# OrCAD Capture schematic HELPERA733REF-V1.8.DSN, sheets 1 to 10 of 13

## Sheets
1 00 Change log: title: HELPERA733_REF; rev: V1.8; company: szBaijie; note: Revision History
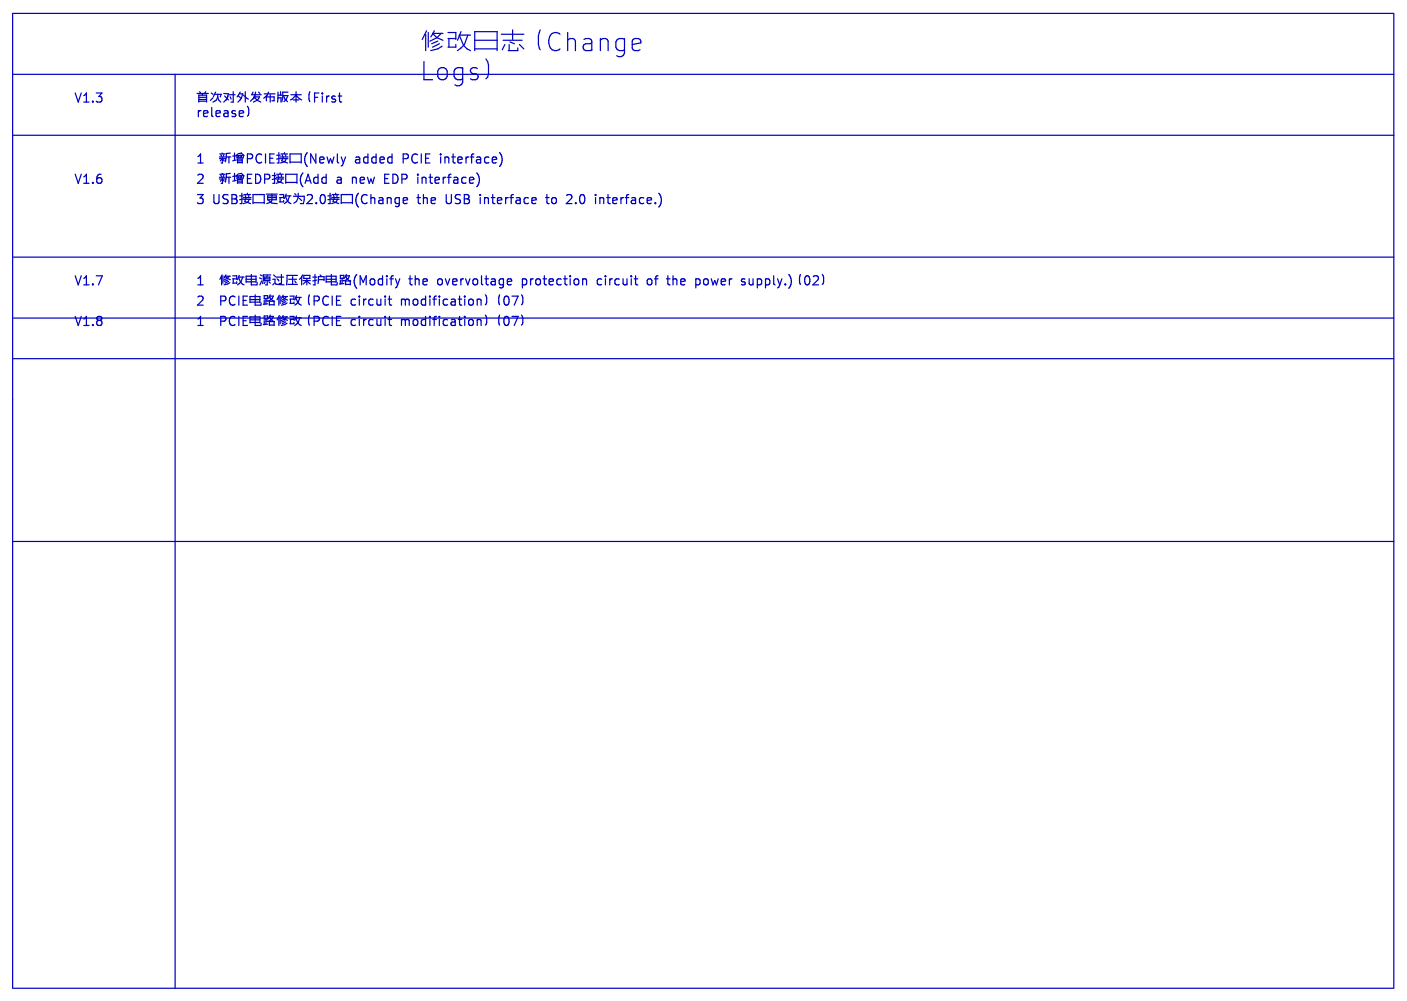
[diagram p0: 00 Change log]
2 01 CORE: size C; note: Core
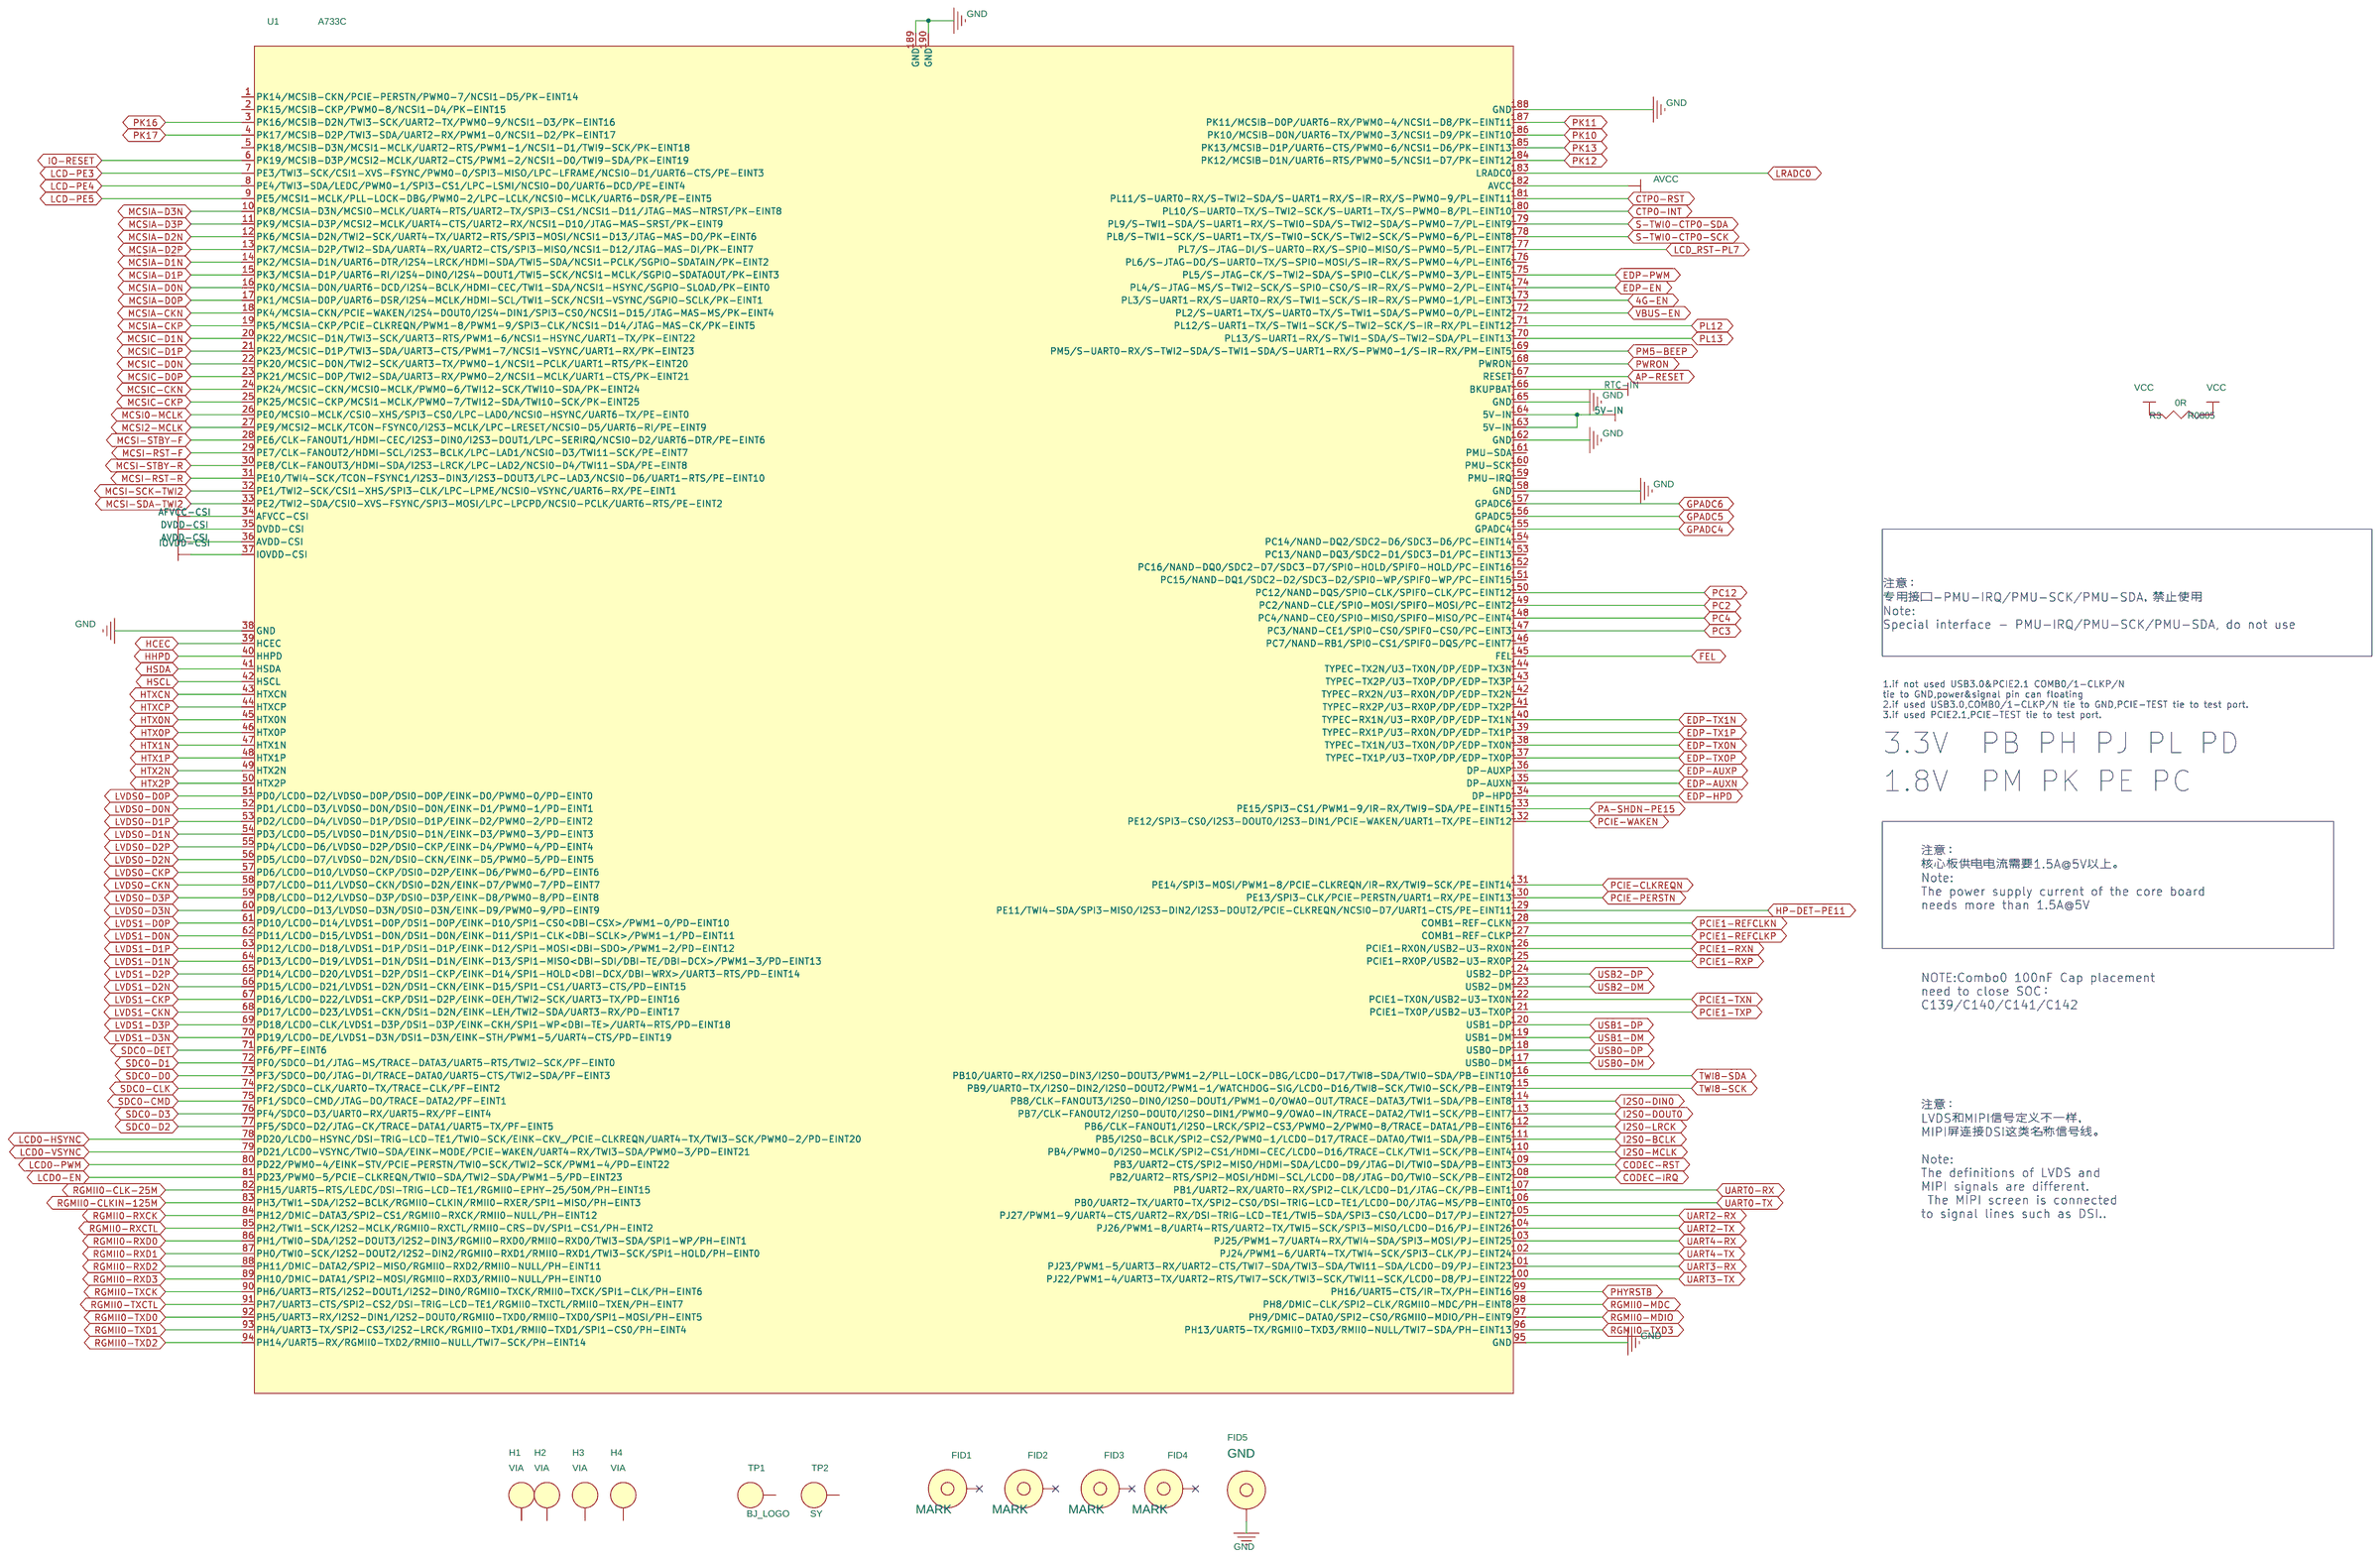
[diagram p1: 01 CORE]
3 02 Power: size B; note: Power
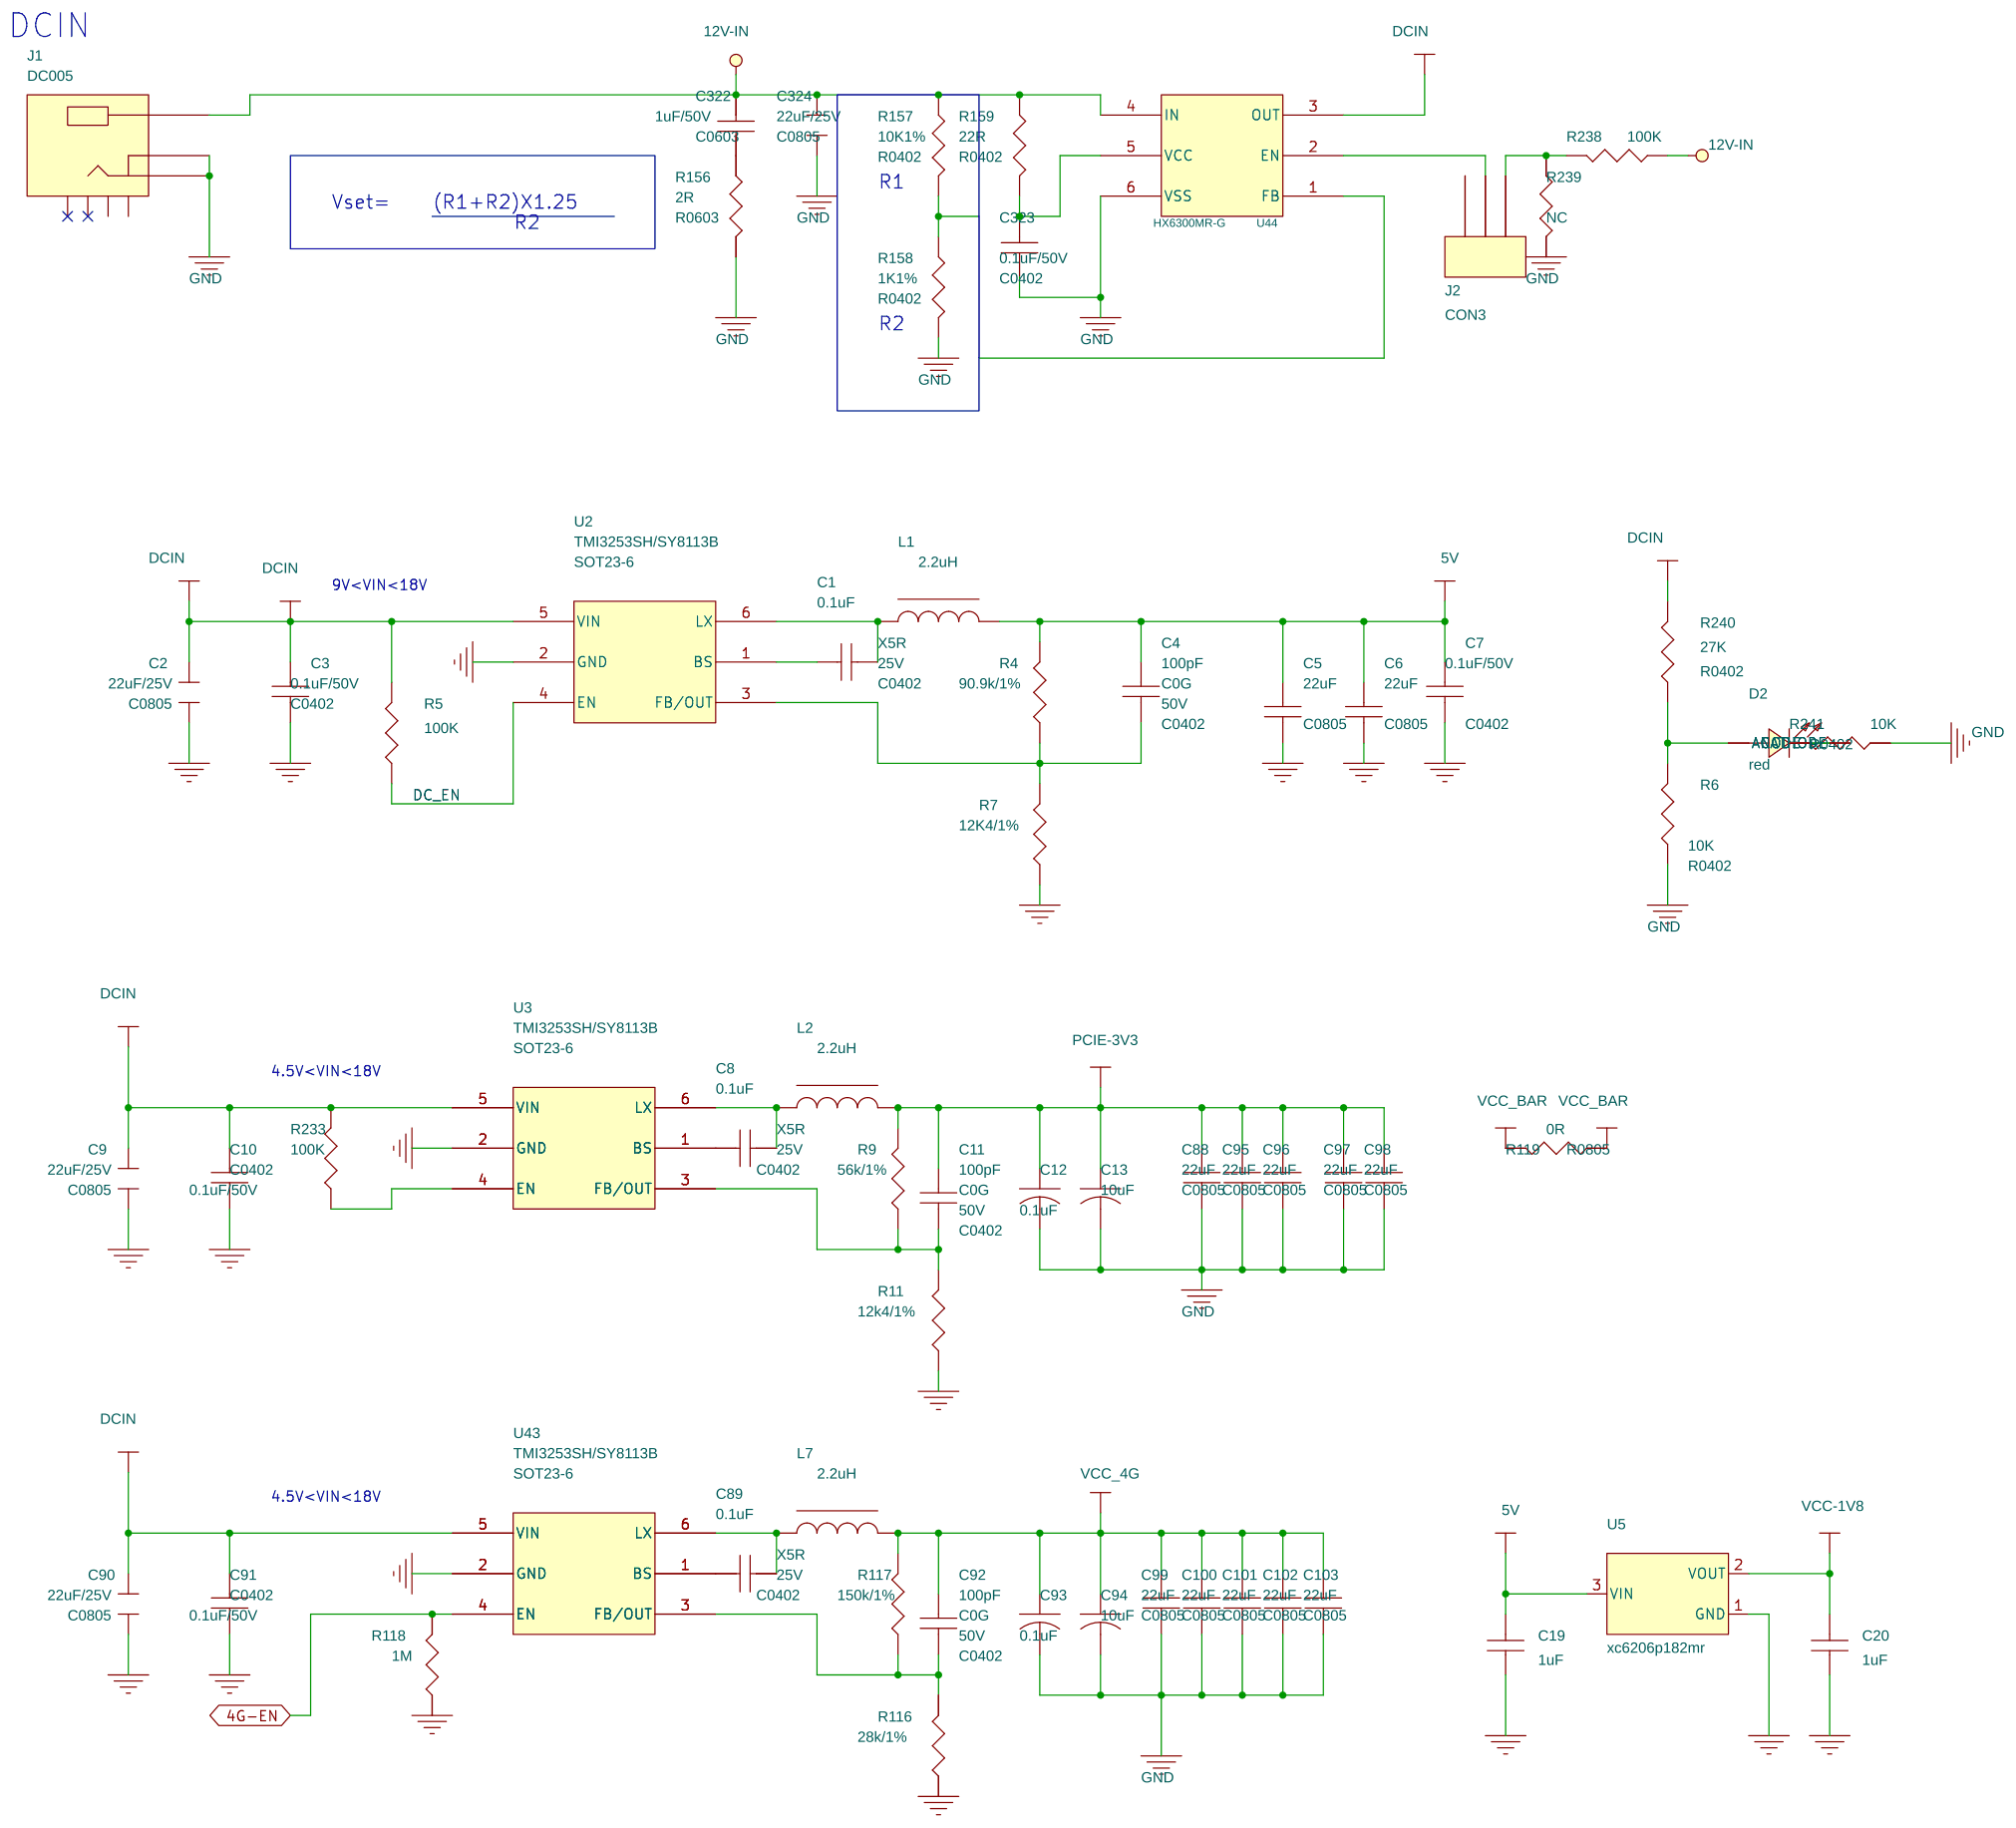
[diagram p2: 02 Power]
4 03 CAMERA: size Custom; note: Camera
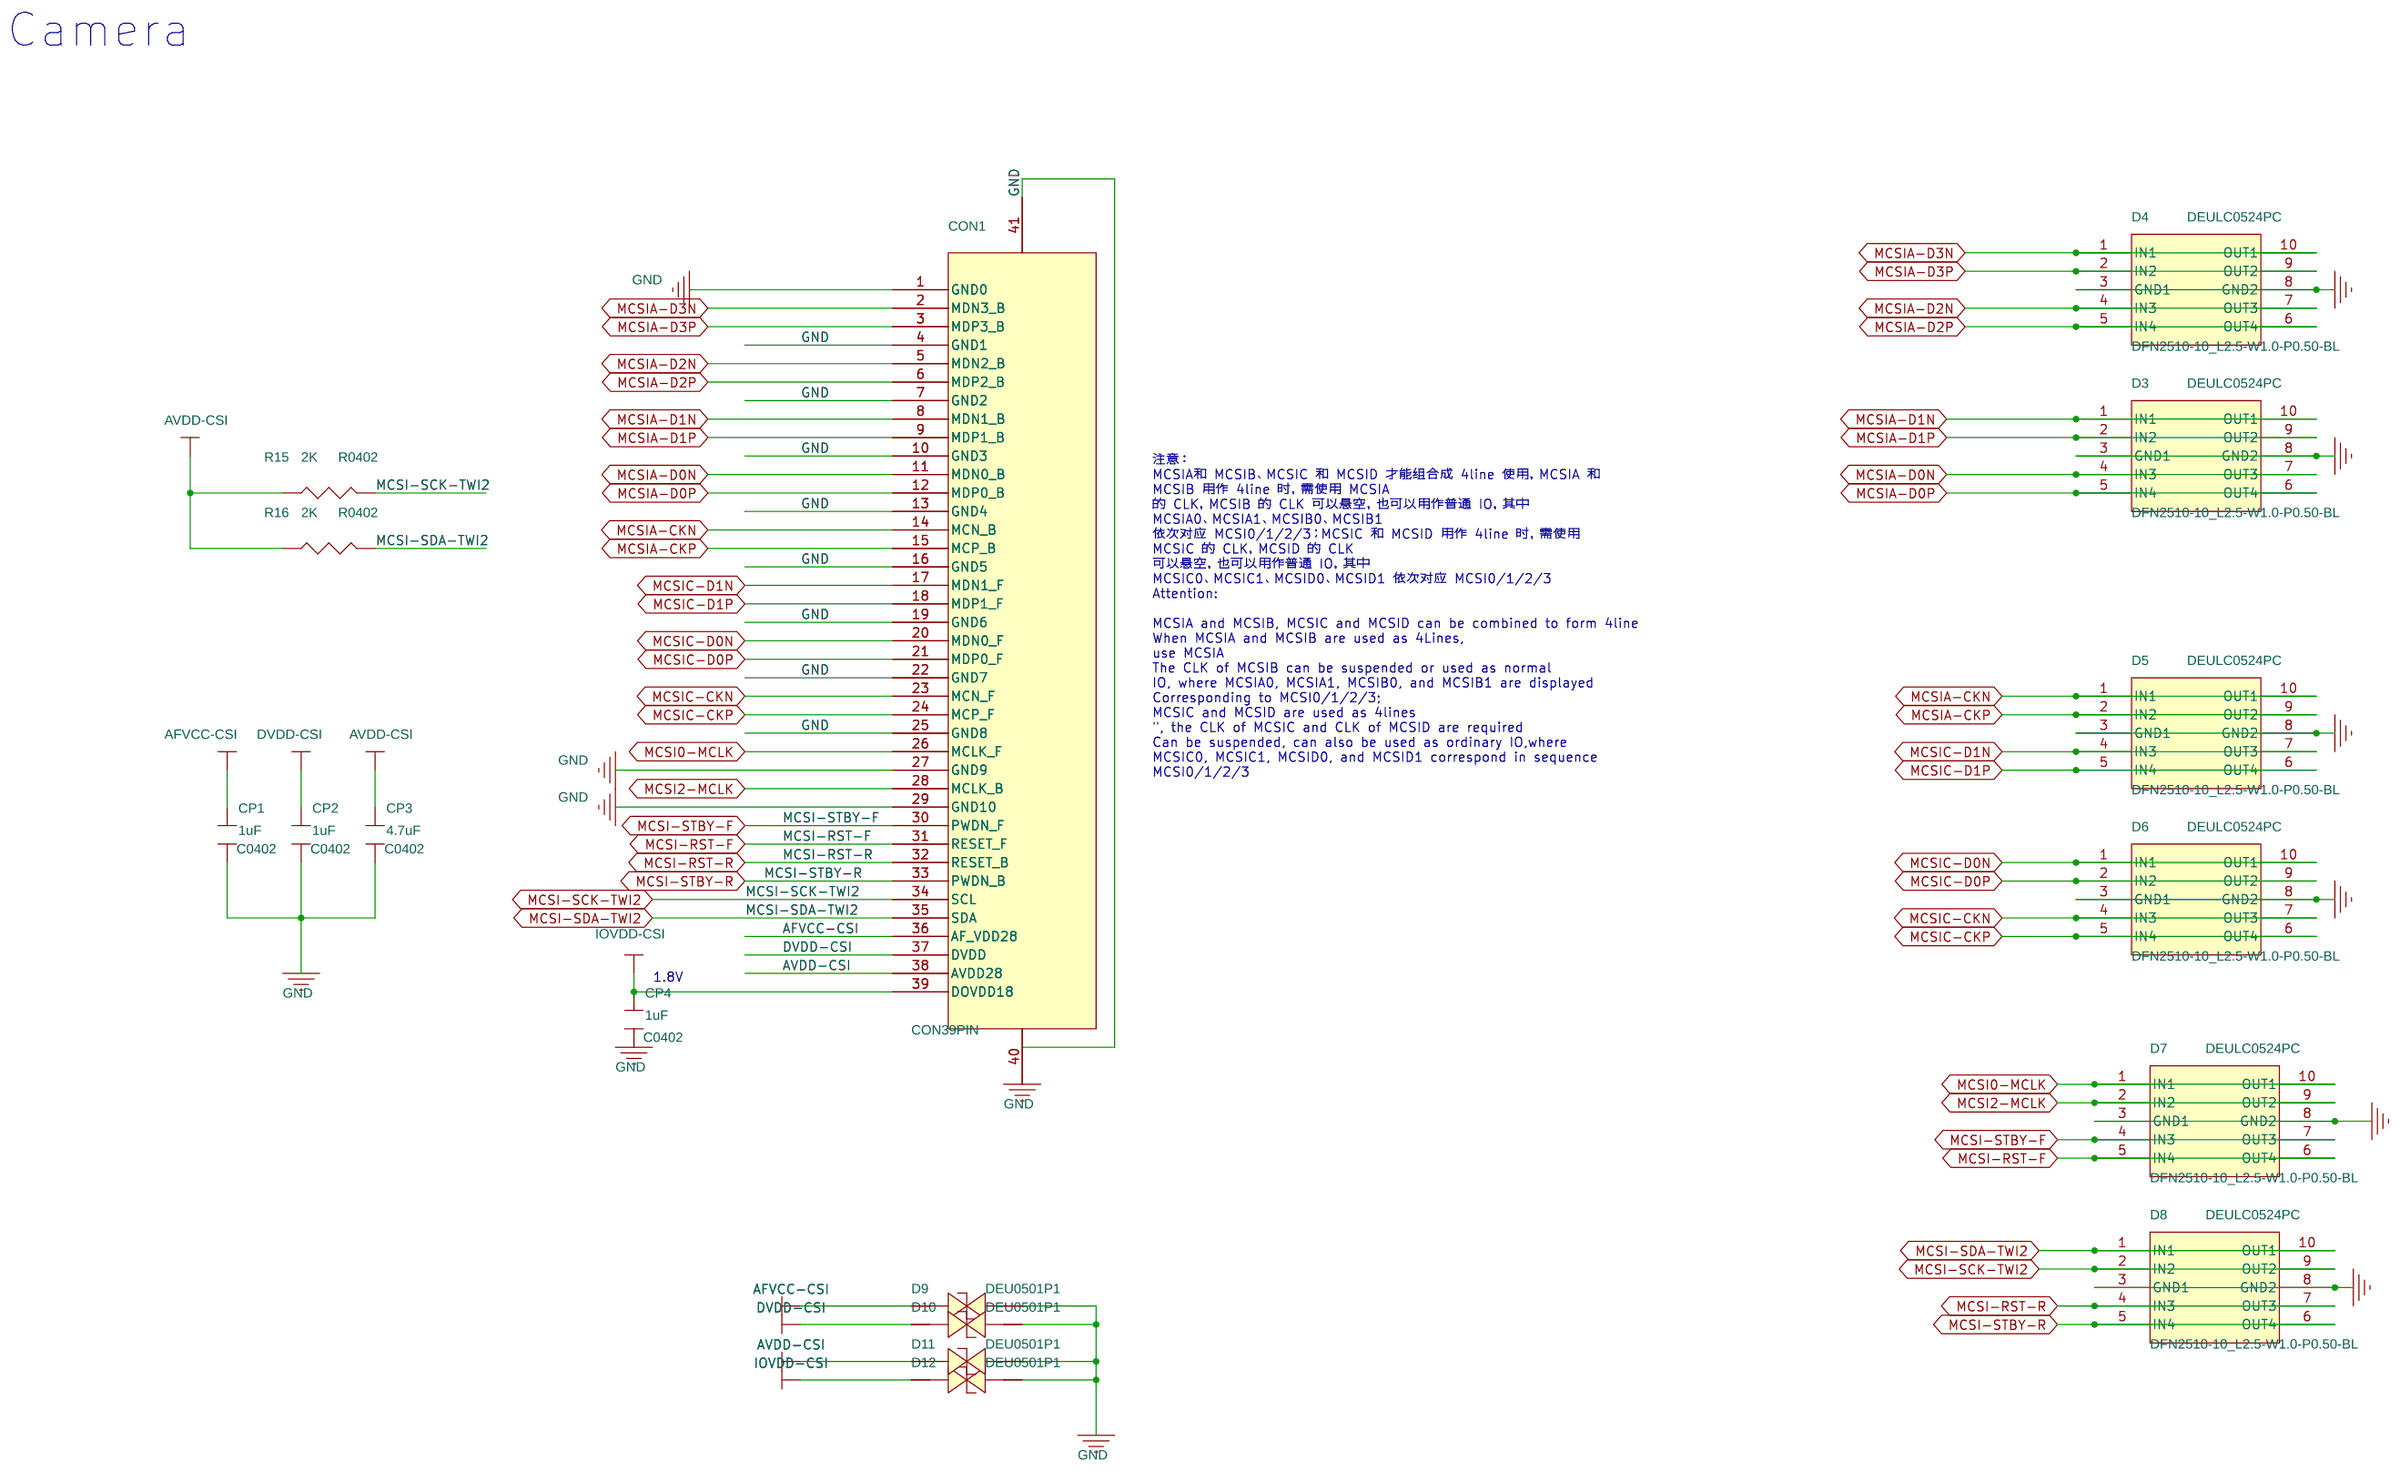
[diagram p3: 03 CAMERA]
5 04 LCD: size C; note: LCD
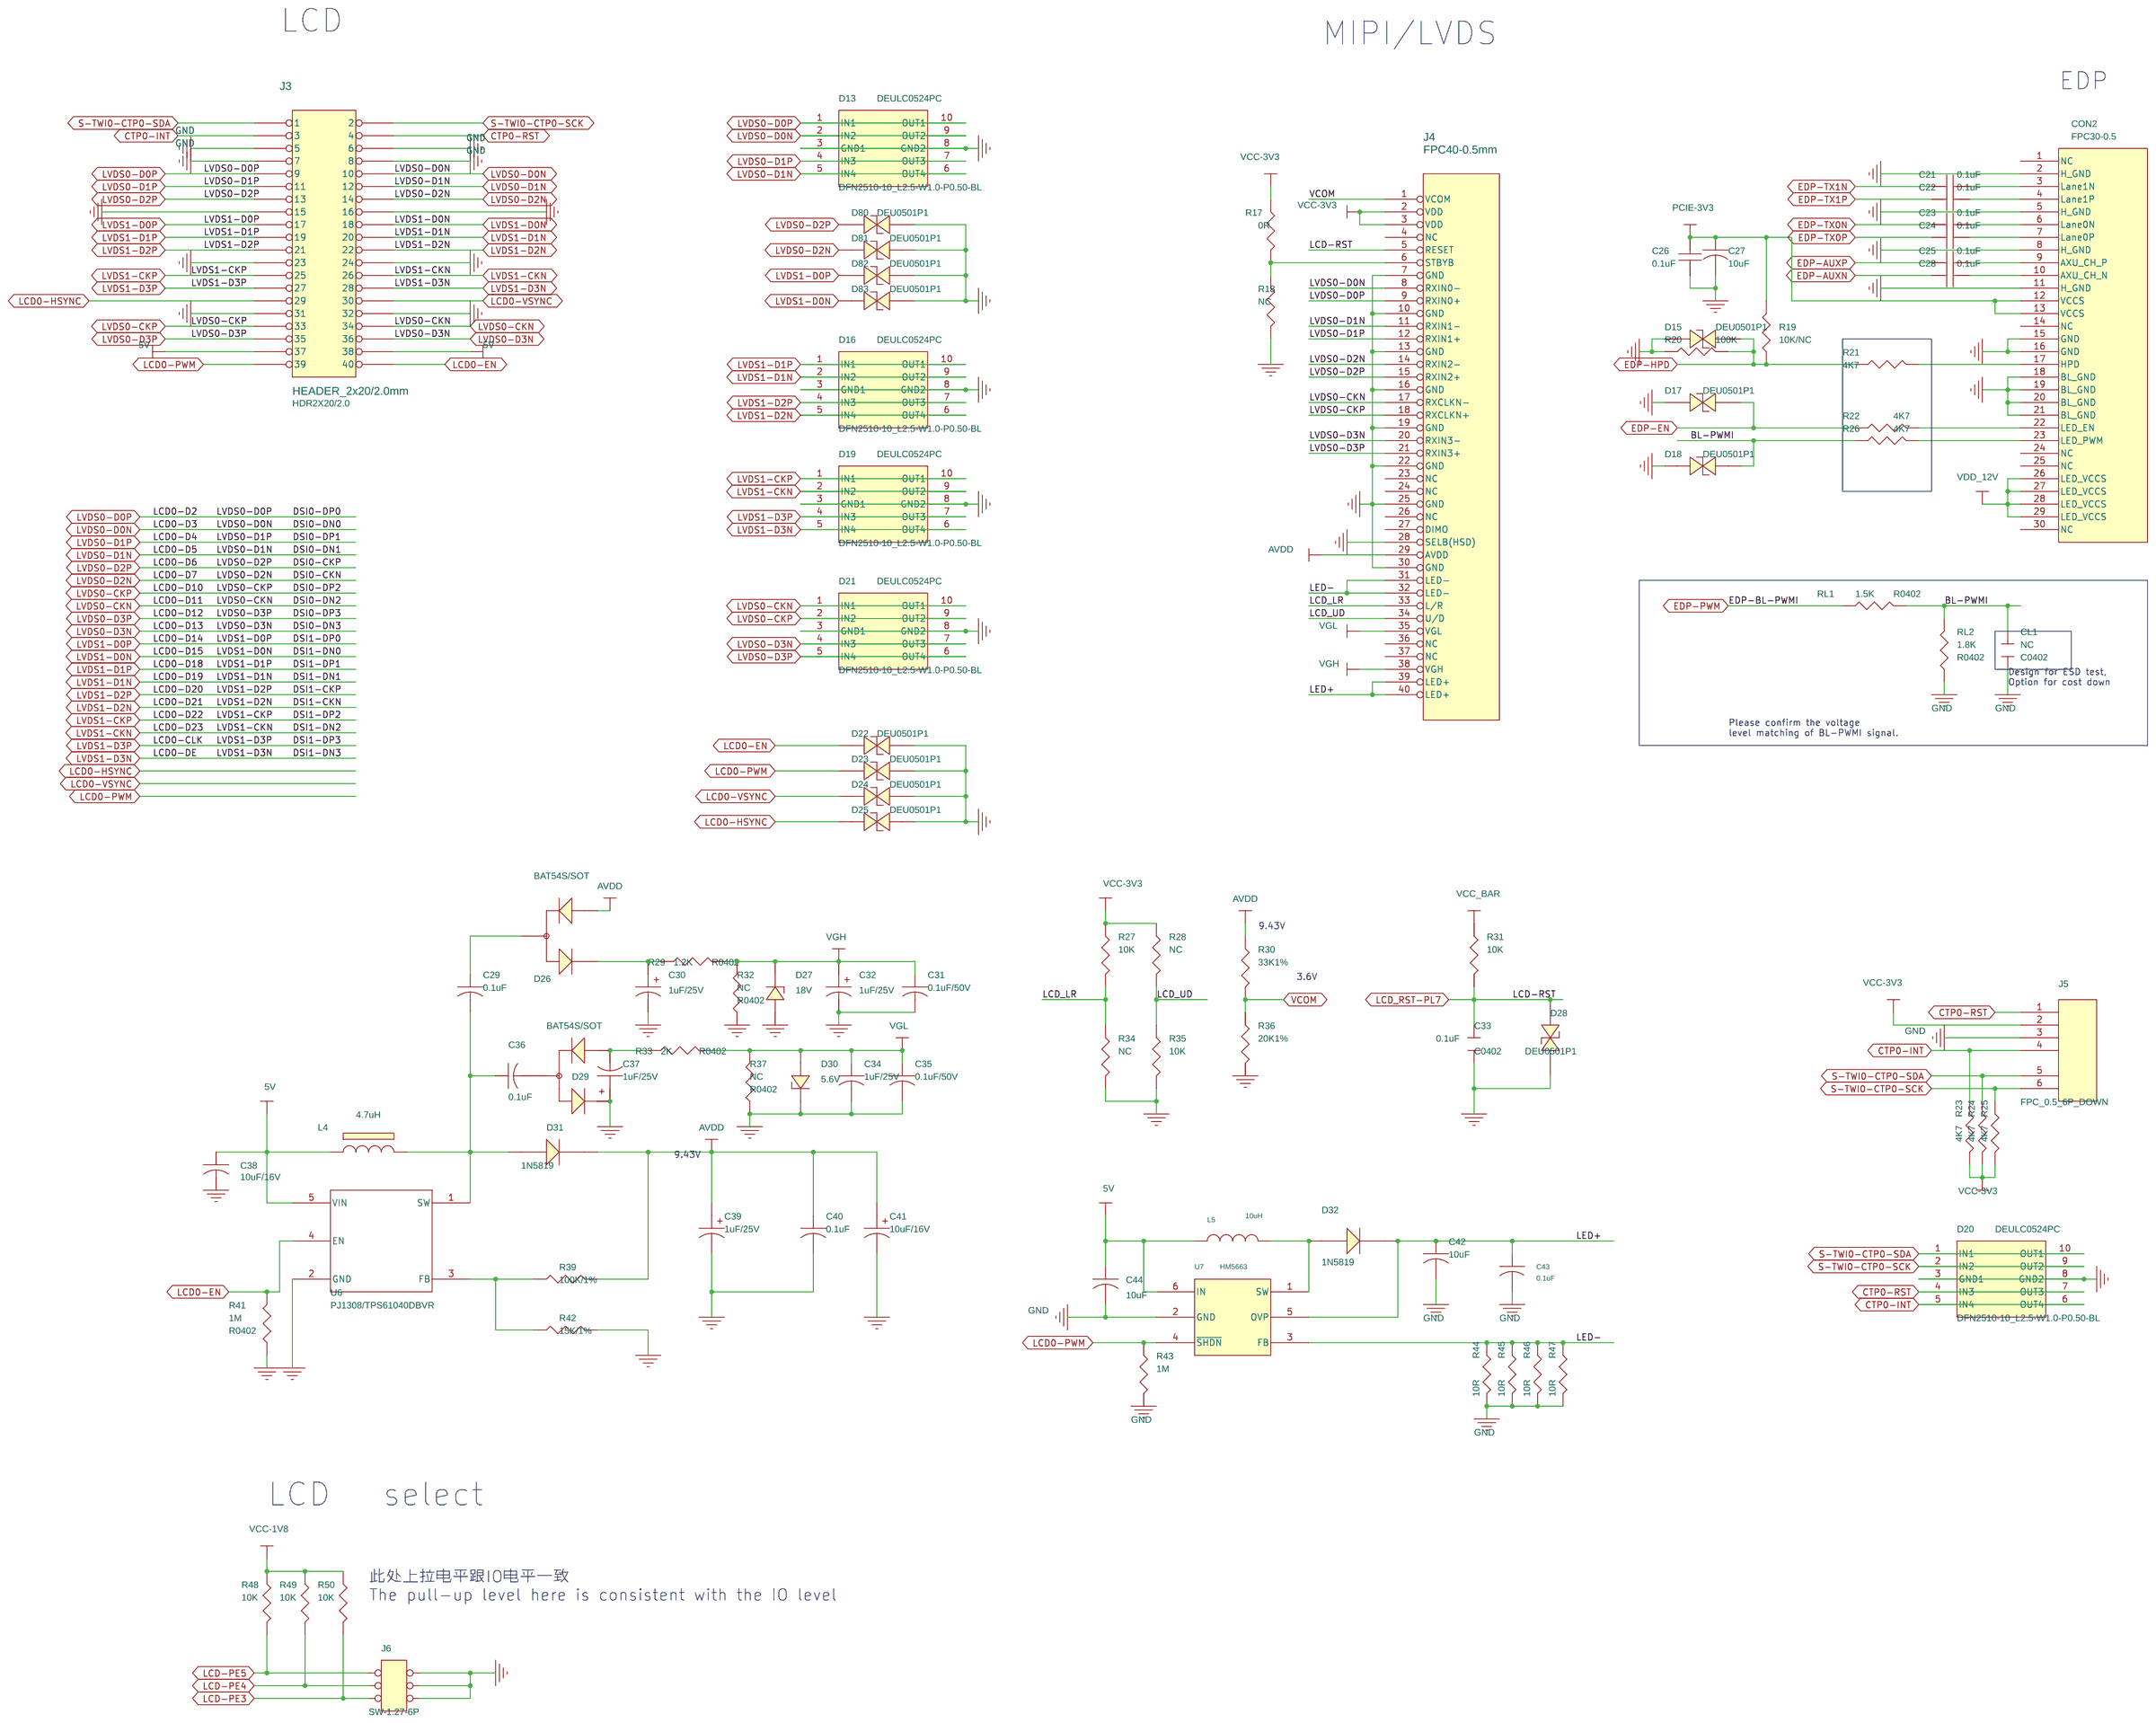
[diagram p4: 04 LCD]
6 10 Ethernet: size B; note: Ethernet
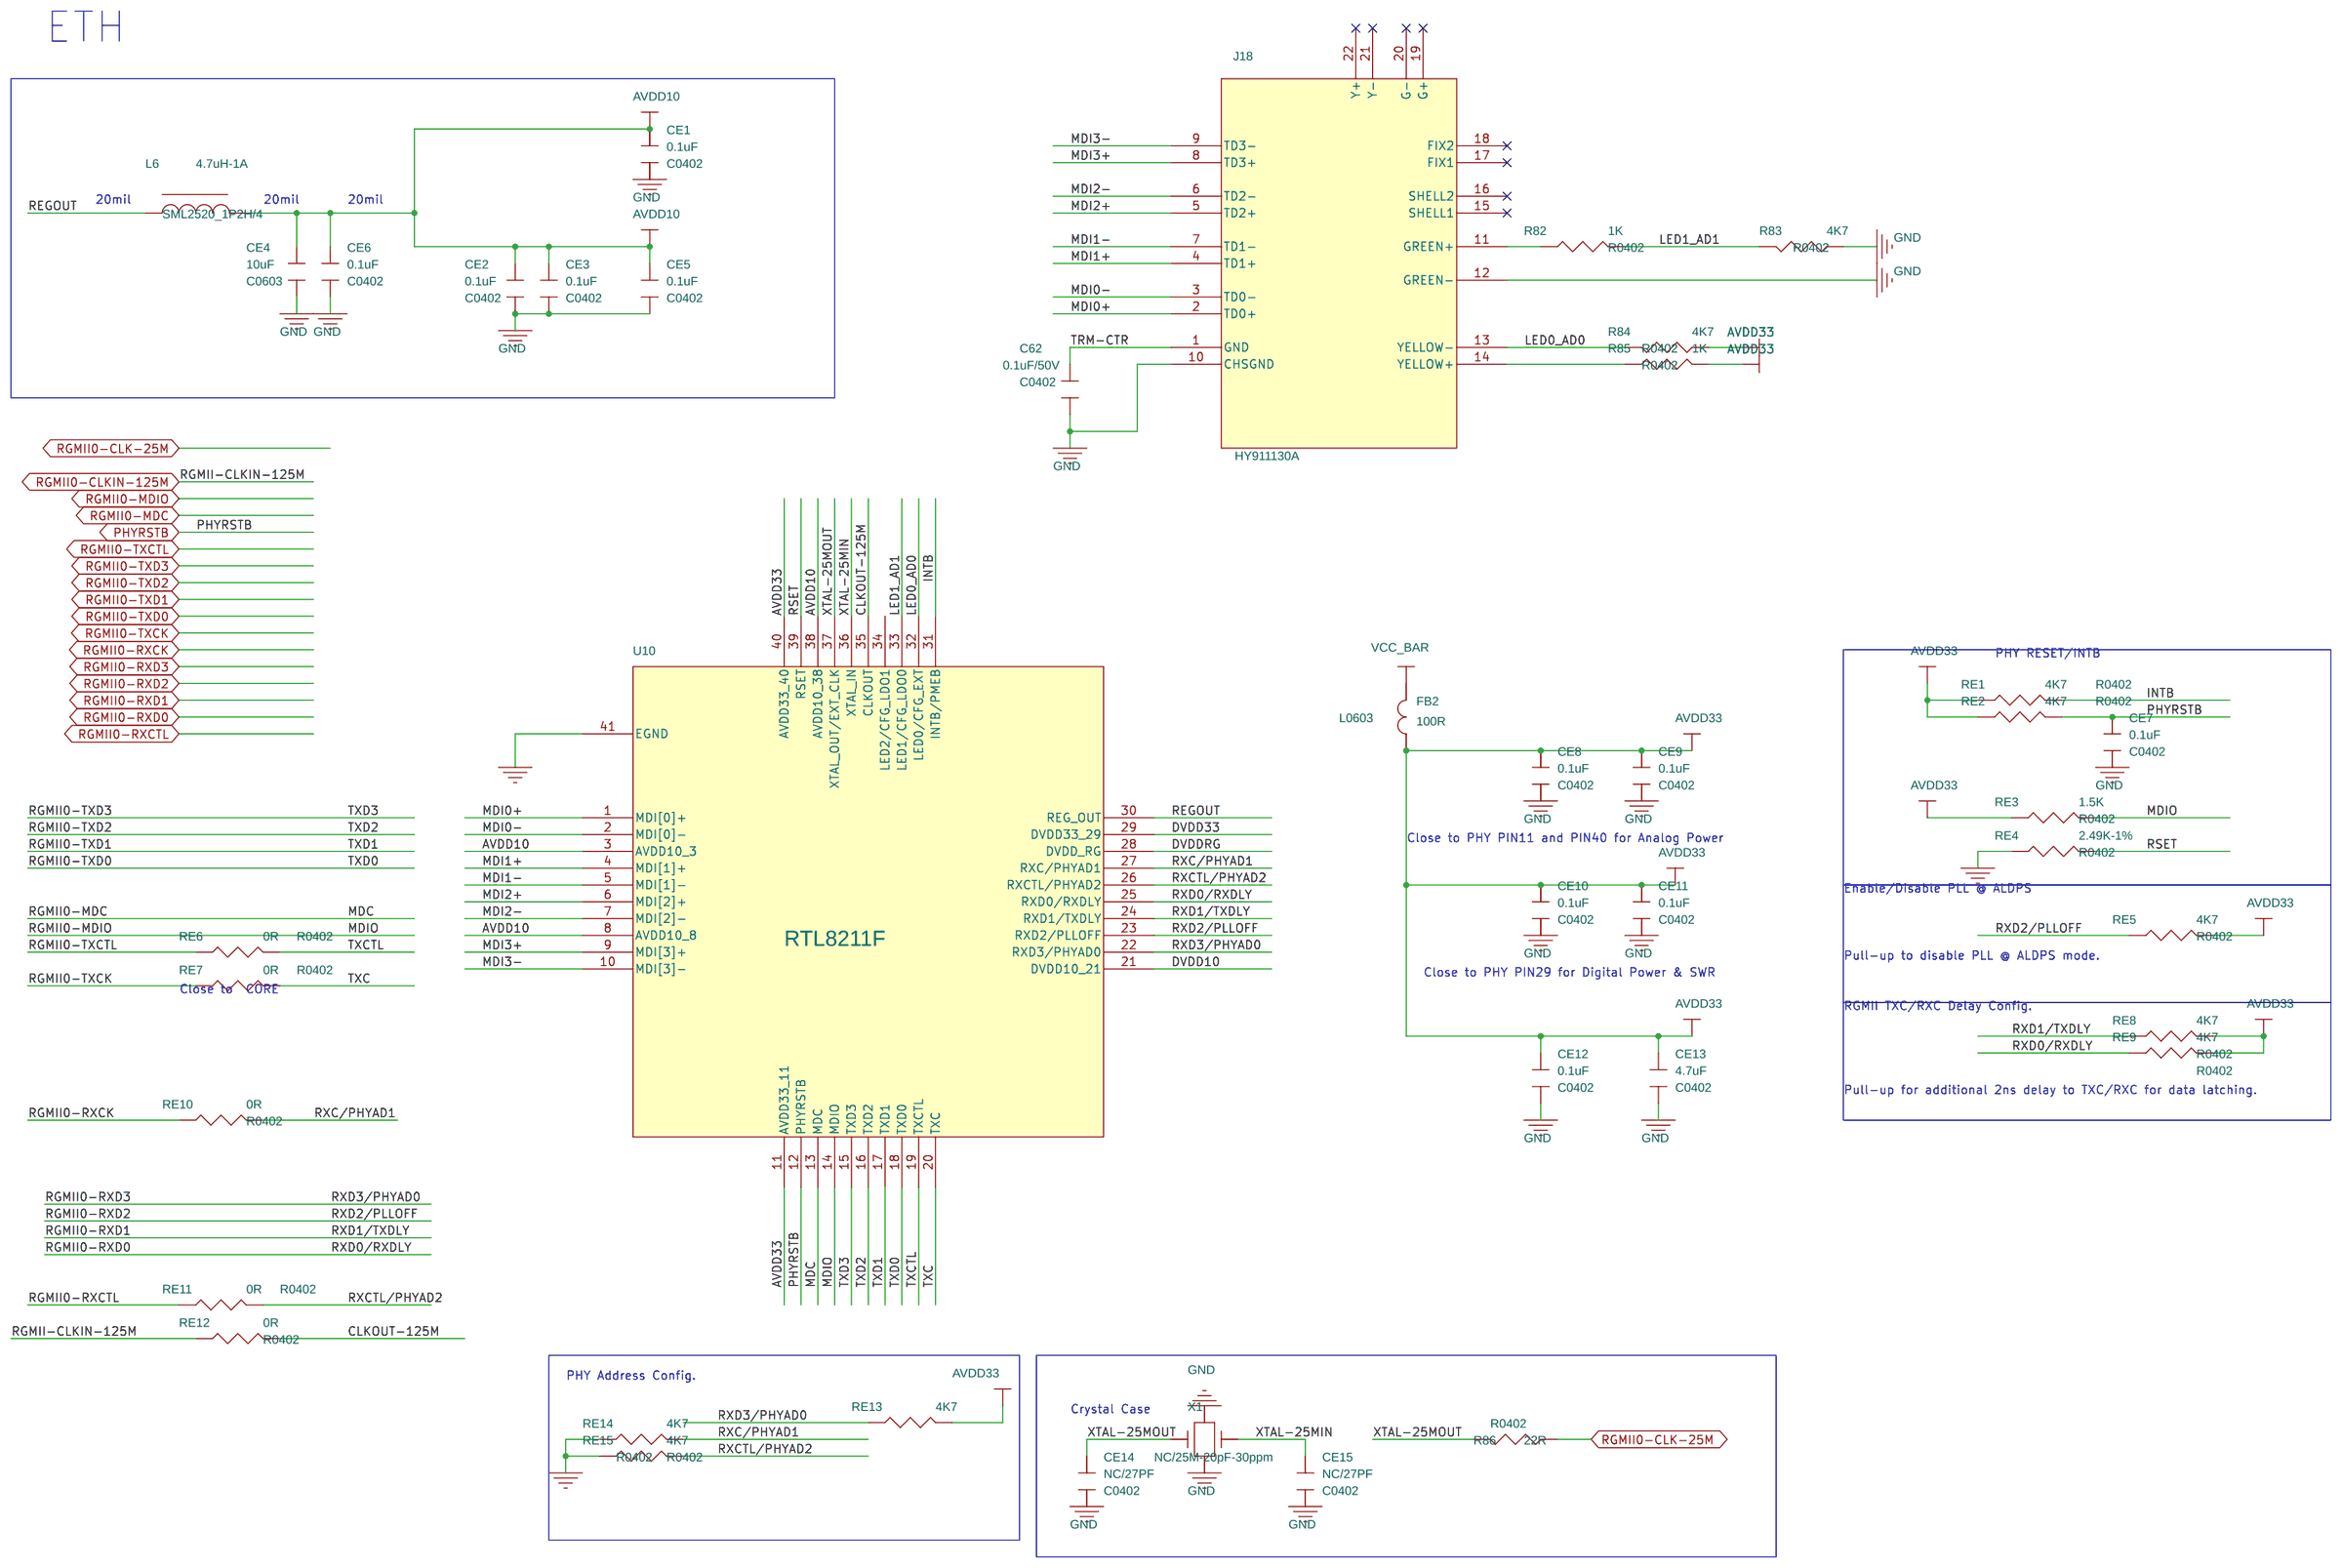
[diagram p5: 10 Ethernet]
7 12 HDMI: size A; note: HDMI
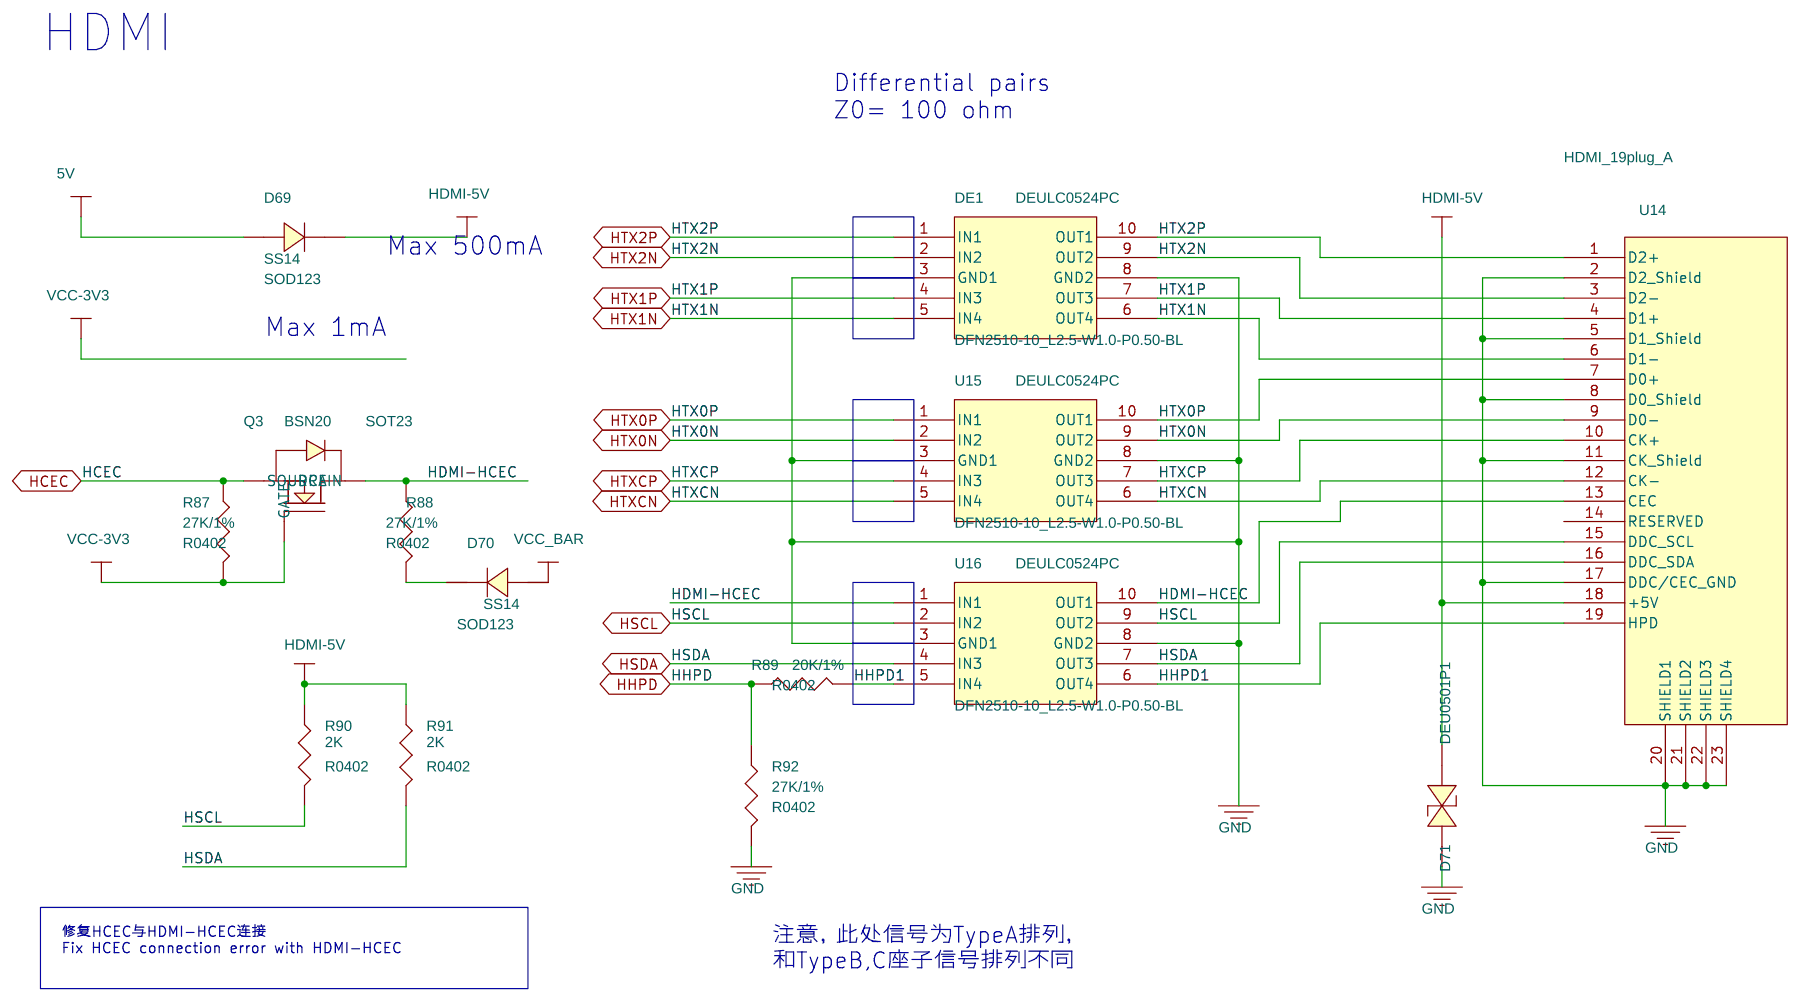
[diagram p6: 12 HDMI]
8 08  UART/485: size A; note: UART/485
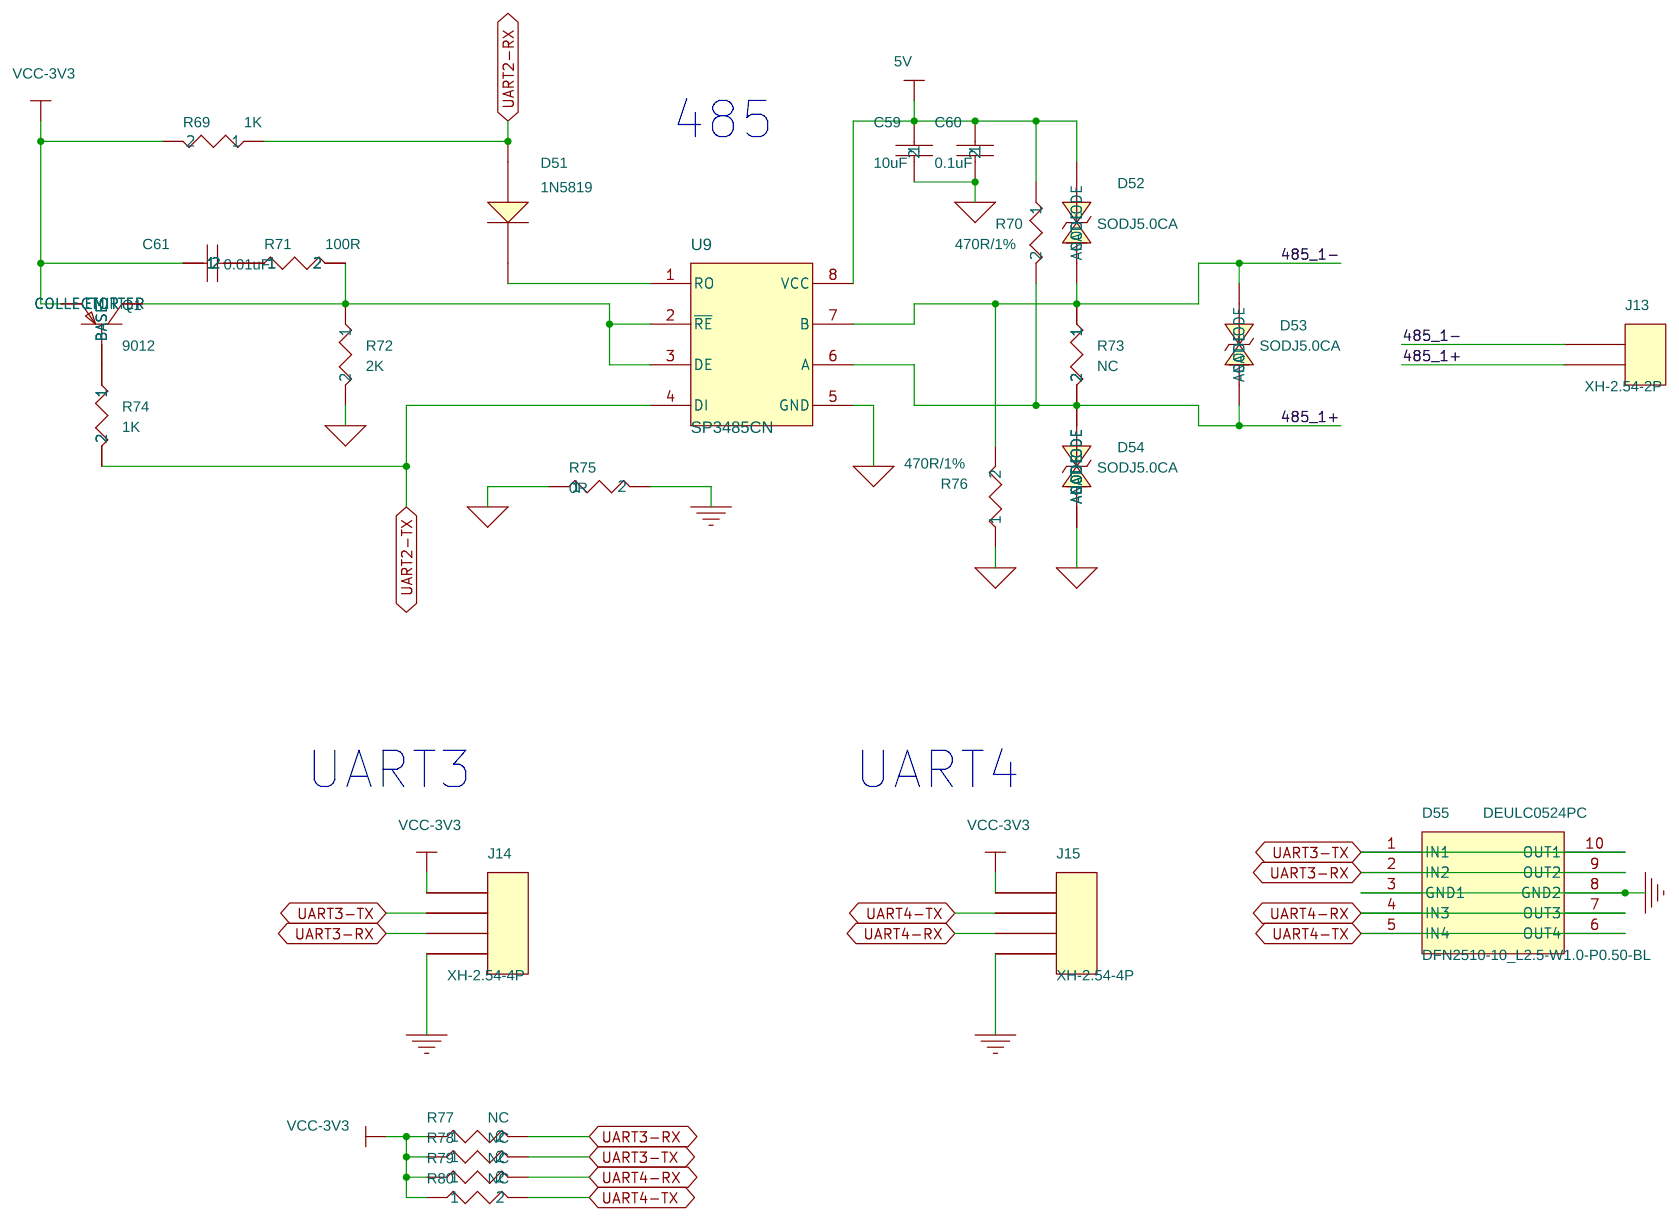
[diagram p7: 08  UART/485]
9 09 IO/ADC/BEEP: size A; note: IO/ADC/BEEP
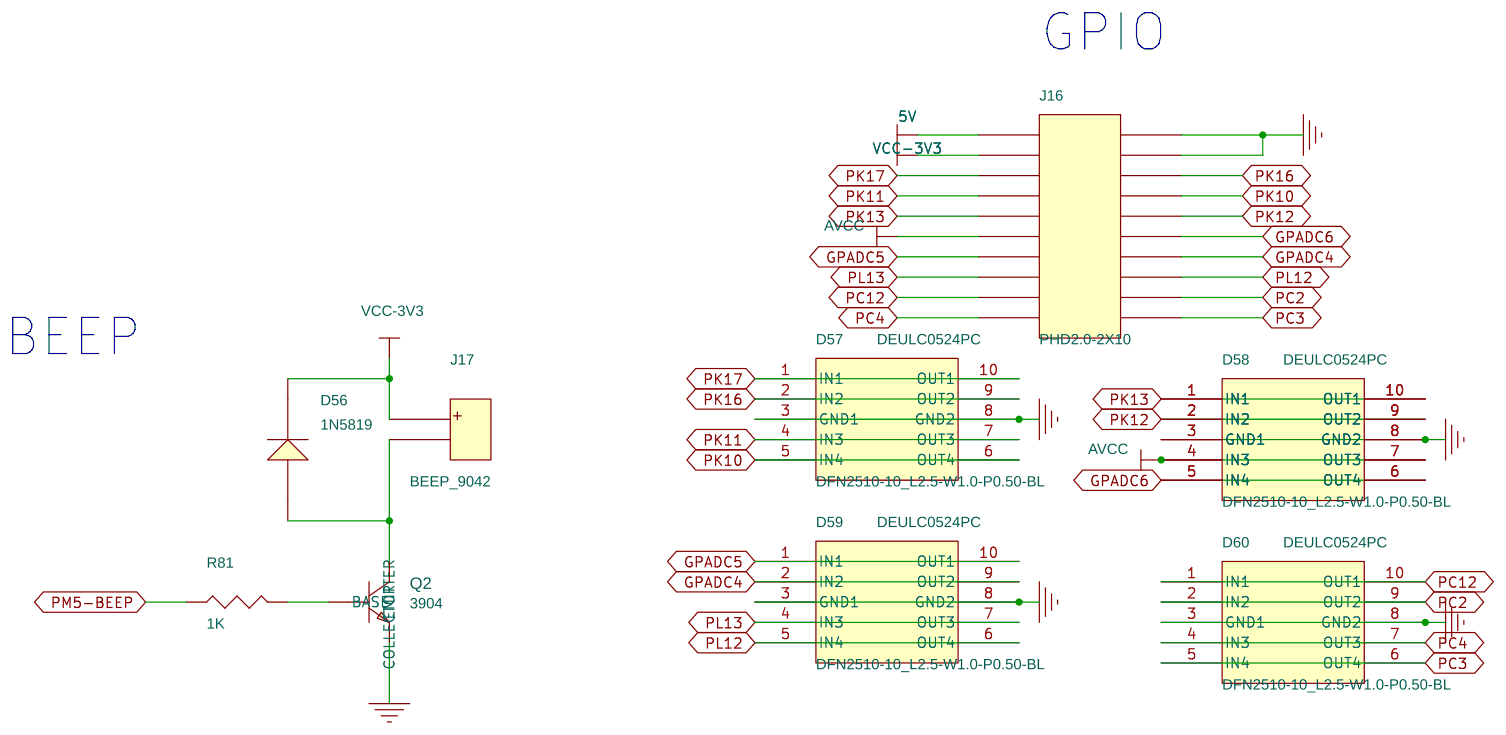
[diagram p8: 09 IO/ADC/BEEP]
10 05 TF/KEY/RTC: size B; note: TF/KEY/RTC
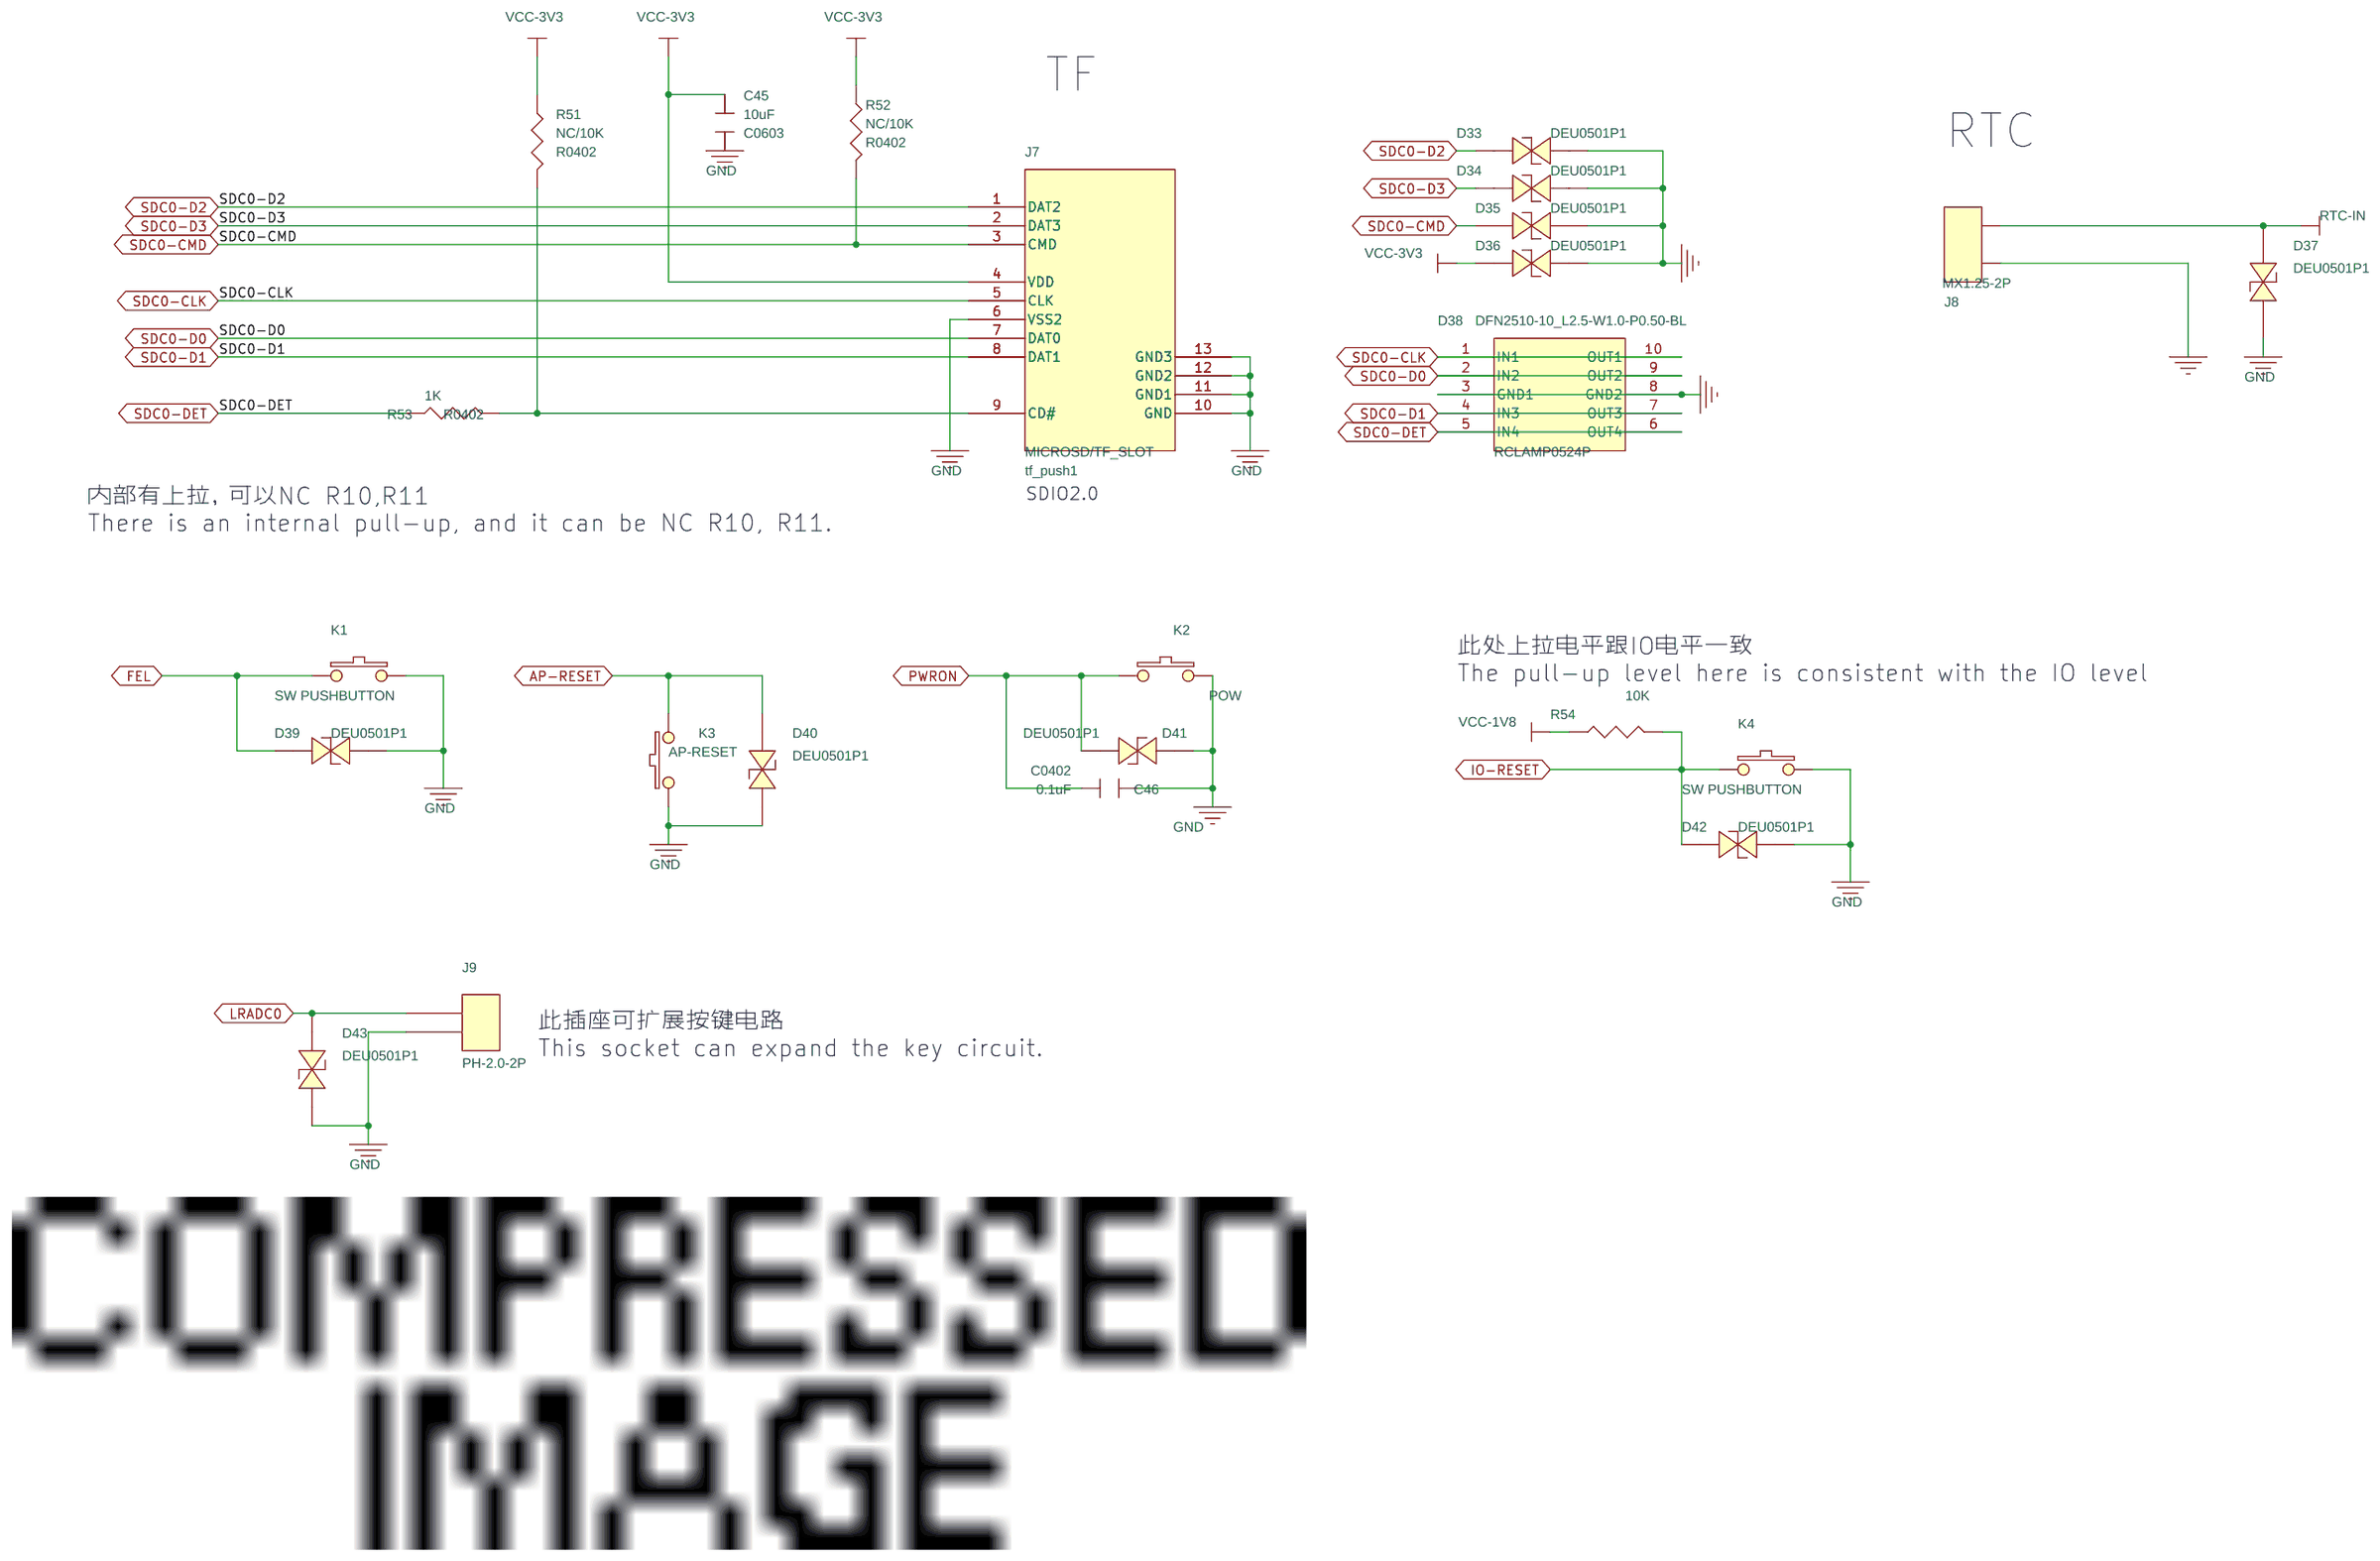
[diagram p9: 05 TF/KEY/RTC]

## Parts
sheet 01 CORE
FID1  MARK  [MARK]
FID2  MARK  [MARK]
FID3  MARK  [MARK]
FID4  MARK  [MARK]
FID5  GND  [DV]
H1  VIA  [DV]
H2  VIA  [DV]
H3  VIA  [DV]
H4  VIA  [DV]
R3  0R  [R0805]
TP1  BJ_LOGO  [BJ_LOGO]
TP2  SY  [6X6]
U1  A733C  [HELPERA733D-2]
sheet 02 Power
C1  0.1uF  [C0402]
C2  22uF/25V  [C0805]
C3  0.1uF/50V  [C0402]
C4  100pF  [C0402]
C5  22uF  [C0805]
C6  22uF  [C0805]
C7  0.1uF/50V  [C0402]
C8  0.1uF  [C0402]
C9  22uF/25V  [C0805]
C10  0.1uF/50V  [C0402]
C11  100pF  [C0402]
C12  0.1uF  [C0402]
C13  10uF  [C0603]
C19  1uF  [C0402]
C20  1uF  [C0402]
C88  22uF  [C0805]
C89  0.1uF  [C0402]
C90  22uF/25V  [C0805]
C91  0.1uF/50V  [C0402]
C92  100pF  [C0402]
C93  0.1uF  [C0402]
C94  10uF  [C0603]
C95  22uF  [C0805]
C96  22uF  [C0805]
C97  22uF  [C0805]
C98  22uF  [C0805]
C99  22uF  [C0805]
C100  22uF  [C0805]
C101  22uF  [C0805]
C102  22uF  [C0805]
C103  22uF  [C0805]
C322  1uF/50V  [C0603]
C323  0.1uF/50V  [C0402]
C324  22uF/25V  [C0805]
D2  red  [D0603]
J1  DC005  [DC470]
J2  CON3  [SS-12F44(1P2T)]
L1  2.2uH  [4018]
L2  2.2uH  [4018]
L7  2.2uH  [4018]
R4  90.9k/1%  [R0402]
R5  100K  [R0402]
R6  10K  [R0402]
R7  12K4/1%  [R0402]
R9  56k/1%  [R0402]
R11  12k4/1%  [R0402]
R116  28k/1%  [R0402]
R117  150k/1%  [R0402]
R118  1M  [R0402]
R119  0R  [R0805]
R156  2R  [R0603]
R157  10K1%  [R0402]
R158  1K1%  [R0402]
R159  22R  [R0402]
R233  100K  [R0402]
R238  100K  [R0402]
R239  NC  [R0402]
R240  27K  [R0402]
R241  10K  [R0402]
U2  TMI3253SH/SY8113B  [SOT23-6]
U3  TMI3253SH/SY8113B  [SOT23-6]
U5  xc6206p182mr  [SOT23]
U43  TMI3253SH/SY8113B  [SOT23-6]
U44  HX6300MR-G  [SOT23-6]
sheet 03 CAMERA
CON1  CON39PIN  [FH35C-39S-0.3SHW]
CP1  1uF  [C0402]
CP2  1uF  [C0402]
CP3  4.7uF  [C0402]
CP4  1uF  [C0402]
D3  DEULC0524PC  [DFN2510-10_L2.5-W1.0-P0.50-BL]
D4  DEULC0524PC  [DFN2510-10_L2.5-W1.0-P0.50-BL]
D5  DEULC0524PC  [DFN2510-10_L2.5-W1.0-P0.50-BL]
D6  DEULC0524PC  [DFN2510-10_L2.5-W1.0-P0.50-BL]
D7  DEULC0524PC  [DFN2510-10_L2.5-W1.0-P0.50-BL]
D8  DEULC0524PC  [DFN2510-10_L2.5-W1.0-P0.50-BL]
D9  DEU0501P1  [ESD0402]
D10  DEU0501P1  [ESD0402]
D11  DEU0501P1  [ESD0402]
D12  DEU0501P1  [ESD0402]
R15  2K  [R0402]
R16  2K  [R0402]
sheet 04 LCD
C21  0.1uF  [C0402]
C22  0.1uF  [C0402]
C23  0.1uF  [C0402]
C24  0.1uF  [C0402]
C25  0.1uF  [C0402]
C26  0.1uF  [C0402]
C27  10uF  [C0603]
C28  0.1uF  [C0402]
C29  0.1uF  [C0402]
C30  1uF/25V  [C0805]
C31  0.1uF/50V  [C0402]
C32  1uF/25V  [C0805]
C33  0.1uF  [C0402]
C34  1uF/25V  [C0805]
C35  0.1uF/50V  [C0402]
C36  0.1uF  [C0402]
C37  1uF/25V  [C0805]
C38  10uF/16V  [C0603]
C39  1uF/25V  [C0805]
C40  0.1uF  [C0402]
C41  10uF/16V  [C0603]
C42  10uF  [C0603]
C43  0.1uF  [C0402]
C44  10uF  [C0603]
CL1  NC  [C0402]
CON2  FPC30-0.5  [FPC30-0.5-1]
D13  DEULC0524PC  [DFN2510-10_L2.5-W1.0-P0.50-BL]
D15  DEU0501P1  [ESD0402]
D16  DEULC0524PC  [DFN2510-10_L2.5-W1.0-P0.50-BL]
D17  DEU0501P1  [ESD0402]
D18  DEU0501P1  [ESD0402]
D19  DEULC0524PC  [DFN2510-10_L2.5-W1.0-P0.50-BL]
D20  DEULC0524PC  [DFN2510-10_L2.5-W1.0-P0.50-BL]
D21  DEULC0524PC  [DFN2510-10_L2.5-W1.0-P0.50-BL]
D22  DEU0501P1  [ESD0402]
D23  DEU0501P1  [ESD0402]
D24  DEU0501P1  [ESD0402]
D25  DEU0501P1  [ESD0402]
D26  BAT54S/SOT  [SOT23]
D27  18V  [D0805]
D28  DEU0501P1  [ESD0402]
D29  BAT54S/SOT  [SOT23]
D30  5.6V  [D0805]
D31  1N5819  [D0805]
D32  1N5819  [SOD323]
D80  DEU0501P1  [ESD0402]
D81  DEU0501P1  [ESD0402]
D82  DEU0501P1  [ESD0402]
D83  DEU0501P1  [ESD0402]
J3  HEADER_2x20/2.0mm  [HDR2X20/2.0]
J4  FPC40-0.5mm  [FPC40-0.5MM-UP]
J5  FPC_0.5_6P_DOWN  [FPC_0.5_6P_DOWN]
J6  SW-1.27-6P  [SW-1.27-6P]
L4  4.7uH  [4018]
L5  10uH  [4018]
R17  0R  [R0402]
R18  NC  [R0402]
R19  10K/NC  [R0402]
R20  100K  [R0402]
R21  4K7  [R0402]
R22  4K7  [R0402]
R23  4K7  [R0402]
R24  4K7  [R0402]
R25  4K7  [R0402]
R26  4K7  [R0402]
R27  10K  [R0402]
R28  NC  [R0402]
R29  1.2K  [R0402]
R30  33K1%  [R0402]
R31  10K  [R0402]
R32  NC  [R0402]
R33  2K  [R0402]
R34  NC  [R0402]
R35  10K  [R0402]
R36  20K1%  [R0402]
R37  NC  [R0402]
R39  100K/1%  [R0402]
R41  1M  [R0402]
R42  15K/1%  [R0402]
R43  1M  [R0402]
R44  10R  [R0402]
R45  10R  [R0402]
R46  10R  [R0402]
R47  10R  [R0402]
R48  10K  [R0402]
R49  10K  [R0402]
R50  10K  [R0402]
RL1  1.5K  [R0402]
RL2  1.8K  [R0402]
U6  PJ1308/TPS61040DBVR  [SOT23-5]
U7  HM5663  [SOT23-6]
sheet 05 TF/KEY/RTC
C45  10uF  [C0603]
C46  0.1uF  [C0402]
D33  DEU0501P1  [ESD0402]
D34  DEU0501P1  [ESD0402]
D35  DEU0501P1  [ESD0402]
D36  DEU0501P1  [ESD0402]
D37  DEU0501P1  [ESD0402]
D38  DFN2510-10_L2.5-W1.0-P0.50-BL  [RCLAMP0524P]
D39  DEU0501P1  [ESD0402]
D40  DEU0501P1  [ESD0402]
D41  DEU0501P1  [ESD0402]
D42  DEU0501P1  [ESD0402]
D43  DEU0501P1  [ESD0402]
J7  MICROSD/TF_SLOT  [tf_push1]
J8  MX1.25-2P  [MX1.25-2P]
J9  PH-2.0-2P  [PH-2.0-2P]
K1  SW PUSHBUTTON  [KEY_3X4]
K2  POW  [KEY_3X4]
K3  AP-RESET  [KEY_3X4]
K4  SW PUSHBUTTON  [KEY_3X4]
R51  NC/10K  [R0402]
R52  NC/10K  [R0402]
R53  1K  [R0402]
R54  10K  [R0402]
sheet 08  UART/485
C59  10uF  [C0603]
C60  0.1uF  [C0402]
C61  0.01uF  [C0402]
D51  1N5819  [SOD323]
D52  SODJ5.0CA  [SOD123]
D53  SODJ5.0CA  [SOD123]
D54  SODJ5.0CA  [SOD123]
D55  DEULC0524PC  [DFN2510-10_L2.5-W1.0-P0.50-BL]
J13  XH-2.54-2P  [XH-2.54-2P]
J14  XH-2.54-4P  [XH-2.54-4P]
J15  XH-2.54-4P  [XH-2.54-4P]
Q1  9012  [SOT23]
R69  1K  [R0402]
R70  470R/1%  [R0402]
R71  100R  [R0402]
R72  2K  [R0402]
R73  NC  [R0402]
R74  1K  [R0402]
R75  0R  [R0402]
R76  470R/1%  [R0402]
R77  NC  [R0402]
R78  NC  [R0402]
R79  NC  [R0402]
R80  NC  [R0402]
U9  SP3485CN  [SO8]
sheet 09 IO/ADC/BEEP
D56  1N5819  [SOD323]
D57  DEULC0524PC  [DFN2510-10_L2.5-W1.0-P0.50-BL]
D58  DEULC0524PC  [DFN2510-10_L2.5-W1.0-P0.50-BL]
D59  DEULC0524PC  [DFN2510-10_L2.5-W1.0-P0.50-BL]
D60  DEULC0524PC  [DFN2510-10_L2.5-W1.0-P0.50-BL]
J16  PHD2.0-2X10  [PHD2.0-2X10]
J17  BEEP_9042  [BEEP_9042]
Q2  3904  [SOT23]
R81  1K  [R0402]
sheet 10 Ethernet
C62  0.1uF/50V  [C0402]
CE1  0.1uF  [C0402]
CE2  0.1uF  [C0402]
CE3  0.1uF  [C0402]
CE4  10uF  [C0603]
CE5  0.1uF  [C0402]
CE6  0.1uF  [C0402]
CE7  0.1uF  [C0402]
CE8  0.1uF  [C0402]
CE9  0.1uF  [C0402]
CE10  0.1uF  [C0402]
CE11  0.1uF  [C0402]
CE12  0.1uF  [C0402]
CE13  4.7uF  [C0402]
CE14  NC/27PF  [C0402]
CE15  NC/27PF  [C0402]
FB2  100R  [L0603]
J18  HY911130A  [HY911130A]
L6  4.7uH-1A  [SML2520_1P2H/4]
R82  1K  [R0402]
R83  4K7  [R0402]
R84  4K7  [R0402]
R85  1K  [R0402]
R86  22R  [R0402]
RE1  4K7  [R0402]
RE2  4K7  [R0402]
RE3  1.5K  [R0402]
RE4  2.49K-1%  [R0402]
RE5  4K7  [R0402]
RE6  0R  [R0402]
RE7  0R  [R0402]
RE8  4K7  [R0402]
RE9  4K7  [R0402]
RE10  0R  [R0402]
RE11  0R  [R0402]
RE12  0R  [R0402]
RE13  4K7  [R0402]
RE14  4K7  [R0402]
RE15  4K7  [R0402]
U10  RTL8211F  [QFN40]
X1  NC/25M-20pF-30ppm  [X3225]
sheet 12 HDMI
D69  SS14  [SOD123]
D70  SS14  [SOD123]
D71  DEU0501P1  [ESD0402]
DE1  DEULC0524PC  [DFN2510-10_L2.5-W1.0-P0.50-BL]
Q3  BSN20  [SOT23]
R87  27K/1%  [R0402]
R88  27K/1%  [R0402]
R89  20K/1%  [R0402]
R90  2K  [R0402]
R91  2K  [R0402]
R92  27K/1%  [R0402]
U14  HDMI_19plug_A  [HDMIQ]
U15  DEULC0524PC  [DFN2510-10_L2.5-W1.0-P0.50-BL]
U16  DEULC0524PC  [DFN2510-10_L2.5-W1.0-P0.50-BL]

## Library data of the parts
FID1-FID5 = T_POINT_R_2: FIDUCAL MARK; COMPONENT_WEIGHT: 30
H1-H4 = T_POINT_R_1: HOLE
R3 R6 R17-R28 R30 R31 R34-R36 R39 R42-R54 R81-R86 R89 R119 R156-R159 R240 R241 = R
TP1 TP2 = T_POINT_R_1
U1 = AO4409_5
C1 C3 C8 C10 C22-C25 C28 C89 C91 = CAP_NP_3: cap,100.00nF,+/-10%,25V,X5R,C0402; Created by: JJJ; Dielectric: X5R; Priority: A; Tolerance: 10%; Voltage: 25V
C2 C9 C33 C46 C62 C90 C324 = CAPACITOR_0
C4 C11 C88 C92 C95-C103 = CAP_NP_3: cap,100.00pF,+/-5%,50V,C0G,C0402; Created by: JJJ; Dielectric: C0G; Priority: A; Tolerance: 5%; Voltage: 50V
C5 C6 = CAP_NP_3: cap,22.00uF,+/-10%,10V,X5R,C0805; Created by: JJJ; Dielectric: X5R; Priority: A; Tolerance: 10%; Voltage: 10V
C7 = CAP_NP_3: cap,100.00nF,+/-10%,16V,X5R,C0402; Created by: JJJ; Dielectric: X5R; Priority: A; Tolerance: 10%; Voltage: 16V
C12 C93 = CAPACITOR
C13 C94 = CAPACITOR_0_v3
C19 C20 C26 = CAP_NP_0: Status: Taiwan
C322 = CAP_NP
C323 = CAP_NP_1
D2 = LED_0
J1 = PHONOJACK_3: ￠3.5DC电源座　前插后贴　5PIN，两定位柱，高4.7mm; PART NUMBER: ZDC-BCT05-1000; SPREADWIN PN: E10000040A; Vendor: 质友
J2 = CON3
L1 L2 L7 = ind1: Power Inductor,3.3uH,0.2,IND_404030; Created by: YTL; DC Resistor: 0.04ohm; Irms: 2.4A; Isat: 3.3A; Priority: A; Resonace frequency: 38M; Tolerance: 20%
R4 R5 R7 R9 R11 R116-R118 R233 R238 R239 = RESISTOR_1: RES,thick film,47KOhm,+/-5%,1/16W,SMD0402
U2 U3 U43 = DCDC_SY8113: Created by: JJJ; Priority: A
U5 = SGM2028_0
U44 = PT4110_0
CON1 = CON39PIN_0
CP1-CP4 = C-C0603-X5R_1: Parameter: C0402-X5R
D3-D8 D13 D16 D19-D21 D38 D55 D57-D60 DE1 U15 U16 = rRClamp0524P
D9-D12 D15 D17 D18 D22-D25 D28 D33-D37 D39-D43 D71 D80-D83 = 1_1.5KE100A: 1ST PART DESCRIPTION: WILL ESD9B5V Bidirection ESD Protection
R15 R16 = R-R0402-1%
C21 = CAP_NP_1: cap,100.00nF,+/-10%,25V,X5R,C0402; Created by: JJJ; Dielectric: X5R; Priority: A; Tolerance: 10%; Voltage: 25V
C27 C29 C31 C34-C36 C38 C40 C42 C44 = C_v2
C30 C32 C37 C39 C41 = CAP_POL
C43 = C
CL1 = C-C0402: Parameter: C0402-X5R
CON2 = CN_2
D26 D29 = BAT54S_SOT
D27 D30 = DIODE_BREAKDOWN_1
D31 D32 D51 D56 = BAS21_SOT_1
J3 = HEADER_20X2_1: Populate: YES
J4 = HEADER_20X2_3: Populate: YES
J5 = connet_0
J6 = CON4_4
L4 = CHOKE_TORROID-FERRITE
L5 = INDUCTOR_v2
R29 R32 R33 R37 R41 R87 R88 R90-R92 = RESISTOR
RE1-RE15 RL1 RL2 = R-R0402-5%
U6 = X9C102_SO_2
U7 = PT4110_0_v2
C45 = CAPACITOR_0: PAGE: 2
J7 = SDMMC_SLOT_0
J8 = CON6_0
J9 = CON2
K1-K4 = SW_PUSHBUTTON
C59 = C0603
C60 = C0402
C61 = C0402_1
D52-D54 = ESD_DIODE: TVS diode;DC Working Voltage(VDC):16.0V;Clamping Voltage(VCL)Ipeak = 1A,8/20£gs:290V Maximum;Capacitance(C)@1MHz, 1V:2pF Typic
J13 = CON4_3_v2
J14 J15 = CON4
Q1 = 2N3906_0
R69 = R0402_11
R70 = R0402_3
R71 = R0402_10
R72 = R0402_1
R73 = R0402
R74 = R0402_7
R75 = R0402_2
R76 = R0402_4
R77 = R0402_8
R78 = R0402_9
R79 = R0402_6
R80 = R0402_5
U9 = SP3485
J16 = CON24A_3
J17 = CON2_0_v2
Q2 = 2N3904_0
CE1-CE15 = C-C0402
FB2 = INDUCTOR_0_v2: RoHS BEAD/600ohm 100Mhz Z=600Ω DCR<0.2Ω 800mA SMT L0603; Package: SMT; Pin Names Rotate: TRUE; Pin Names Visible: FALSE; Pin Numbers Visible: TRUE
J18 = HY911130A
L6 = L-L2016
U10 = 8211F
X1 = 3224
D69 D70 = D_0: Allegro PCB Footprint: d2513A
Q3 = NMOS_0
U14 = HDMI_A

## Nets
5V: C4.1 C5.1 C6.1 C7.1 C19.2 C38.1 C44.1 C59.1 C60.1 D52.2(CATHODE) D69.1 J3.37 J3.38 J16.1 L1.2 L4.1 L5.1 R3.1 R4.1 R70.1 U5.3(VIN) U6.5(VIN) U7.6(IN) U9.8(VCC) ; also on sheet 12 13
5V-IN: R3.2 U1.163(5V-IN) U1.164(5V-IN)
12V-IN: C322.2 C324.1 J1.1 R157.1 R159.1 R238.2 U44.4(IN)
AVCC: D58.4(IN3) D58.7(OUT3) J16.11 U1.182(AVCC) ; also on sheet 13
AVDD: C39.1 C40.1 C41.1 D26.1 D31.2(CATHODE) J4.29(AVDD) R30.1 R39.2
AVDD10: CE1.2 CE2.2 CE3.2 CE4.2 CE5.2 CE6.2 L6.2 U10.3(AVDD10) U10.8(AVDD10) U10.21(DVDD10) U10.38(AVDD10)
AVDD33: CE8.2 CE9.2 CE10.2 CE11.2 CE12.2 CE13.2 FB2.2 R84.1 R85.2 RE1.1 RE2.1 RE3.1 RE5.2 RE8.2 RE9.2 RE13.2 U10.11(AVDD33) U10.28(DVDD_RG) U10.29(DVDD33) U10.40(AVDD33)
AVDD-CSI: CON1.38(AVDD28) CP3.1 D11.2(CATHODE) R15.1 R16.1 U1.36(AVDD-CSI)
DVDD-CSI: CON1.37(DVDD) CP2.1 D10.2(CATHODE) U1.35(DVDD-CSI)
GND: C2.2 C3.2 C5.2 C6.2 C7.2 C9.2 C10.2 C12.2 C13.2 C19.1 C20.1 C26.1 C27.2 C30.2 C31.2 C32.2 C33.1 C34.2 C35.2 C37.1 C38.2 C39.2 C40.2 C41.2 C42.2 C43.2 C44.2 C45.1 C46.2 C62.1 C88.2 C90.2 C91.2 C93.2 C94.2 C95.2 C96.2 C97.2 C98.2 C99.2 C100.2 C101.2 C102.2 C103.2 C323.1 C324.2 CE1.1 CE2.1 CE3.1 CE4.1 CE5.1 CE6.1 CE7.1 CE8.1 CE9.1 CE10.1 CE11.1 CE12.1 CE13.1 CE14.1 CE15.1 CL1.2 CON1.1(GND0) CON1.4(GND1) CON1.7(GND2) CON1.10(GND3) CON1.13(GND4) CON1.16(GND5) CON1.19(GND6) CON1.22(GND7) CON1.25(GND8) CON1.27(GND9) CON1.29(GND10) CON1.40 CON1.41 CON2.2(H_GND) CON2.5(H_GND) CON2.8(H_GND) CON2.11(H_GND) CON2.15(GND) CON2.16(GND) CON2.18(BL_GND) CON2.19(BL_GND) CON2.20(BL_GND) CON2.21(BL_GND) CP1.2 CP2.2 CP3.2 CP4.2 D3.3(GND1) D3.8(GND2) D4.3(GND1) D4.8(GND2) D5.3(GND1) D5.8(GND2) D6.3(GND1) D6.8(GND2) D7.3(GND1) D7.8(GND2) D8.3(GND1) D8.8(GND2) D9.1(ANODE) D10.1(ANODE) D11.1(ANODE) D12.1(ANODE) D13.3(GND1) D13.8(GND2) D15.1(ANODE) D16.3(GND1) D16.8(GND2) D17.1(ANODE) D18.1(ANODE) D19.3(GND1) D19.8(GND2) D20.3(GND1) D20.8(GND2) D21.3(GND1) D21.8(GND2) D22.2(CATHODE) D23.2(CATHODE) D24.2(CATHODE) D25.2(CATHODE) D27.1(ANODE) D28.2(CATHODE) D29.2 D30.2(CATHODE) D33.1(ANODE) D34.1(ANODE) D35.1(ANODE) D36.1(ANODE) D37.1(ANODE) D38.3(GND1) D38.8(GND2) D39.2(CATHODE) D40.1(ANODE) D41.1(ANODE) D42.2(CATHODE) D43.1(ANODE) D55.3(GND1) D55.8(GND2) D57.3(GND1) D57.8(GND2) D58.3(GND1) D58.8(GND2) D59.3(GND1) D59.8(GND2) D60.3(GND1) D60.8(GND2) D71.2(CATHODE) D80.2(CATHODE) D81.2(CATHODE) D82.2(CATHODE) D83.2(CATHODE) DE1.3(GND1) DE1.8(GND2) FID5.1(TP) J1.2 J1.3 J3.5 J3.6 J3.7 J3.8 J3.15 J3.16 J3.23 J3.24 J3.31 J3.32 J4.7(GND) J4.10(GND) J4.13(GND) J4.16(GND) J4.19(GND) J4.22(GND) J4.25(GND) J4.28(SELB(HSD)) J4.30(GND) J5.3 J6.4 J6.5 J6.6 J7.6(VSS2) J7.10(GND) J7.11(GND1) J7.12(GND2) J7.13(GND3) J8.1 J9.2 J14.4 J15.4 J16.2 J16.4 J18.10(CHSGND) J18.12(GREEN-) K1.2 K2.1 K3.1 K4.2 Q2.2(EMITTER) R6.1 R7.2 R11.2 R18.2 R20.1 R32.1 R34.2 R35.2 R36.2 R37.1 R41.1 R42.2 R43.2 R44.2 R45.2 R46.2 R47.2 R75.2 R83.1 R92.2 R116.2 R118.2 R156.2 R158.2 R239.1 R241.1 RE4.1 RE14.1 RE15.1 RL2.1 U1.38(GND) U1.95(GND) U1.158(GND) U1.162(GND) U1.165(GND) U1.188(GND) U1.189(GND) U1.190(GND) U2.2(GND) U3.2(GND) U5.1(GND) U6.2(GND) U7.2(GND) U10.41(EGND) U14.2(D2_Shield) U14.5(D1_Shield) U14.8(D0_Shield) U14.11(CK_Shield) U14.17(DDC/CEC_GND) U14.20(SHIELD1) U14.21(SHIELD2) U14.22(SHIELD3) U14.23(SHIELD4) U15.3(GND1) U15.8(GND2) U16.3(GND1) U16.8(GND2) U43.2(GND) U44.6(VSS) X1.2 X1.4 ; also on sheet 11 12 13
GND_485: C59.2 C60.2 D54.1(ANODE) R72.2 R75.1 R76.1 U9.5(GND)
VBUS-EN: U1.172(PL2/S-UART1-TX/S-UART0-TX/S-TWI1-SDA/S-PWM0-0/PL-EINT2) ; also on sheet 12
VCC-1V8: C20.2 R48.1 R49.1 R50.1 R54.1 U5.2(VOUT) ; also on sheet 11 13
VCC-3V3: C45.2 C61.1 D36.2(CATHODE) D56.2(CATHODE) D70.1 FB2.1 J4.2(VDD) J4.3(VDD) J5.2 J7.4(VDD) J14.1 J15.1 J16.3 J17.1 Q1.2(EMITTER) Q3.1(GATE) R17.1 R23.2 R24.2 R25.2 R27.1 R28.1 R31.1 R51.1 R52.1 R69.2 R77.1 R78.1 R79.1 R80.1 R87.2 R119.1 ; also on sheet 12 13
VCC_4G: C92.1 C93.1 C94.1 C99.1 C100.1 C101.1 C102.1 C103.1 L7.2 R117.1 ; also on sheet 11
4G-EN: R118.1 U1.173(PL3/S-UART1-RX/S-UART0-RX/S-TWI1-SCK/S-IR-RX/S-PWM0-1/PL-EINT3) U43.4(EN)
485_1+: D53.1(ANODE) D54.2(CATHODE) J13.2 R70.2 R73.2 U9.6(A)
485_1-: D52.1(ANODE) D53.2(CATHODE) J13.1 R73.1 R76.2 U9.7(B)
AFVCC-CSI: CON1.36(AF_VDD28) CP1.1 D9.2(CATHODE) U1.34(AFVCC-CSI)
AP-RESET: D40.2(CATHODE) K3.2 U1.167(RESET)
BL-PWMI: CL1.1 D18.2(CATHODE) R26.1 RL1.2 RL2.2
CLKOUT-125M: RE12.2 U10.35(CLKOUT)
CODEC-IRQ: U1.108(PB2/UART2-RTS/SPI2-MOSI/HDMI-SCL/LCD0-D8/JTAG-DO/TWI0-SCK/PB-EINT2) ; also on sheet 13
CODEC-RST: U1.109(PB3/UART2-CTS/SPI2-MISO/HDMI-SDA/LCD0-D9/JTAG-DI/TWI0-SDA/PB-EINT3) ; also on sheet 13
CTP0-INT: D20.5(IN4) D20.6(OUT4) J3.3 J5.4 R23.1 U1.180(PL10/S-UART0-TX/S-TWI2-SCK/S-UART1-TX/S-PWM0-8/PL-EINT10)
CTP0-RST: D20.4(IN3) D20.7(OUT3) J3.4 J5.1 U1.181(PL11/S-UART0-RX/S-TWI2-SDA/S-UART1-RX/S-IR-RX/S-PWM0-9/PL-EINT11)
DC_EN: R5.2 U2.4(EN)
DCIN: C2.1 C3.1 C9.1 C10.1 C90.1 C91.1 CON2.26(LED_VCCS) CON2.27(LED_VCCS) CON2.28(LED_VCCS) CON2.29(LED_VCCS) R5.1 R233.1 R240.2 U2.5(VIN) U3.5(VIN) U43.5(VIN) U44.3(OUT)
EDP-AUXN: C28.1 U1.135(DP-AUXN)
EDP-AUXP: C25.1 U1.136(DP-AUXP)
EDP-EN: D17.2(CATHODE) R22.1 U1.174(PL4/S-JTAG-MS/S-TWI2-SCK/S-SPI0-CS0/S-IR-RX/S-PWM0-2/PL-EINT4)
EDP-HPD: D15.2(CATHODE) R19.1 R20.2 R21.1 U1.134(DP-HPD)
EDP-PWM: RL1.1 U1.175(PL5/S-JTAG-CK/S-TWI2-SDA/S-SPI0-CLK/S-PWM0-3/PL-EINT5)
EDP-TX0N: C23.1 U1.138(TYPEC-TX1N/U3-TX0N/DP/EDP-TX0N)
EDP-TX0P: C24.1 U1.137(TYPEC-TX1P/U3-TX0P/DP/EDP-TX0P)
EDP-TX1N: C21.1 U1.140(TYPEC-RX1N/U3-RX0P/DP/EDP-TX1N)
EDP-TX1P: C22.1 U1.139(TYPEC-RX1P/U3-RX0N/DP/EDP-TX1P)
FEL: D39.1(ANODE) K1.1 U1.145(FEL)
GPADC4: D59.2(IN2) D59.9(OUT2) J16.14 U1.155(GPADC4)
GPADC5: D59.1(IN1) D59.10(OUT1) J16.13 U1.156(GPADC5)
GPADC6: D58.5(IN4) D58.6(OUT4) J16.12 U1.157(GPADC6)
HCEC: Q3.2(SOURCE) R87.1 U1.39(HCEC)
HDMI-5V: D69.2 D71.1(ANODE) R90.2 R91.2 U14.18(+5V)
HDMI-HCEC: Q3.3(DRAIN) R88.2 U14.13(CEC) U16.1(IN1) U16.10(OUT1)
HHPD: R89.1 R92.1 U1.40(HHPD)
HHPD1: R89.2 U14.19(HPD) U16.5(IN4) U16.6(OUT4)
HP-DET-PE11: U1.129(PE11/TWI4-SDA/SPI3-MISO/I2S3-DIN2/I2S3-DOUT2/PCIE-CLKREQN/NCSI0-D7/UART1-CTS/PE-EINT11) ; also on sheet 13
HSCL: R90.1 U1.42(HSCL) U14.15(DDC_SCL) U16.2(IN2) U16.9(OUT2)
HSDA: R91.1 U1.41(HSDA) U14.16(DDC_SDA) U16.4(IN3) U16.7(OUT3)
HTX0N: U1.45(HTX0N) U14.9(D0-) U15.2(IN2) U15.9(OUT2)
HTX0P: U1.46(HTX0P) U14.7(D0+) U15.1(IN1) U15.10(OUT1)
HTX1N: DE1.5(IN4) DE1.6(OUT4) U1.47(HTX1N) U14.6(D1-)
HTX1P: DE1.4(IN3) DE1.7(OUT3) U1.48(HTX1P) U14.4(D1+)
HTX2N: DE1.2(IN2) DE1.9(OUT2) U1.49(HTX2N) U14.3(D2-)
HTX2P: DE1.1(IN1) DE1.10(OUT1) U1.50(HTX2P) U14.1(D2+)
HTXCN: U1.43(HTXCN) U14.12(CK-) U15.5(IN4) U15.6(OUT4)
HTXCP: U1.44(HTXCP) U14.10(CK+) U15.4(IN3) U15.7(OUT3)
I2S0-BCLK: U1.111(PB5/I2S0-BCLK/SPI2-CS2/PWM0-1/LCD0-D17/TRACE-DATA0/TWI1-SDA/PB-EINT5) ; also on sheet 13
I2S0-DIN0: U1.114(PB8/CLK-FANOUT3/I2S0-DIN0/I2S0-DOUT1/PWM1-0/OWA0-OUT/TRACE-DATA3/TWI1-SDA/PB-EINT8) ; also on sheet 13
I2S0-DOUT0: U1.113(PB7/CLK-FANOUT2/I2S0-DOUT0/I2S0-DIN1/PWM0-9/OWA0-IN/TRACE-DATA2/TWI1-SCK/PB-EINT7) ; also on sheet 13
I2S0-LRCK: U1.112(PB6/CLK-FANOUT1/I2S0-LRCK/SPI2-CS3/PWM0-2/PWM0-8/TRACE-DATA1/PB-EINT6) ; also on sheet 13
I2S0-MCLK: U1.110(PB4/PWM0-0/I2S0-MCLK/SPI2-CS1/HDMI-CEC/LCD0-D16/TRACE-CLK/TWI1-SCK/PB-EINT4) ; also on sheet 13
INTB: RE1.2 U10.31(INTB/PMEB)
IO-RESET: D42.1(ANODE) K4.1 R54.2 U1.6(PK19/MCSIB-D3P/MCSI2-MCLK/UART2-CTS/PWM1-2/NCSI1-D0/TWI9-SDA/PK-EINT19)
IOVDD-CSI: CON1.39(DOVDD18) CP4.1 D12.2(CATHODE) U1.37(IOVDD-CSI)
LCD0-EN: D22.1(ANODE) J3.40 R41.2 U1.81(PD23/PWM0-5/PCIE-CLKREQN/TWI0-SDA/TWI2-SDA/PWM1-5/PD-EINT23) U6.4(EN)
LCD0-HSYNC: D25.1(ANODE) J3.29 U1.78(PD20/LCD0-HSYNC/DSI-TRIG-LCD-TE1/TWI0-SCK/EINK-CKV_/PCIE-CLKREQN/UART4-TX/TWI3-SCK/PWM0-2/PD-EINT20)
LCD0-PWM: D23.1(ANODE) J3.39 R43.1 U1.80(PD22/PWM0-4/EINK-STV/PCIE-PERSTN/TWI0-SCK/TWI2-SCK/PWM1-4/PD-EINT22) U7.4(~{SHDN})
LCD0-VSYNC: D24.1(ANODE) J3.30 U1.79(PD21/LCD0-VSYNC/TWI0-SDA/EINK-MODE/PCIE-WAKEN/UART4-RX/TWI3-SDA/PWM0-3/PD-EINT21)
LCD-PE3: J6.3 R50.2 U1.7(PE3/TWI3-SCK/CSI1-XVS-FSYNC/PWM0-0/SPI3-MISO/LPC-LFRAME/NCSI0-D1/UART6-CTS/PE-EINT3)
LCD-PE4: J6.2 R49.2 U1.8(PE4/TWI3-SDA/LEDC/PWM0-1/SPI3-CS1/LPC-LSMI/NCSI0-D0/UART6-DCD/PE-EINT4)
LCD-PE5: J6.1 R48.2 U1.9(PE5/MCSI1-MCLK/PLL-LOCK-DBG/PWM0-2/LPC-LCLK/NCSI0-MCLK/UART6-DSR/PE-EINT5)
LCD_LR: J4.33(L/R) R27.2 R34.1
LCD_RST-PL7: C33.2 D28.1(ANODE) J4.5(RESET) R31.2 U1.177(PL7/S-JTAG-DI/S-UART0-RX/S-SPI0-MISO/S-PWM0-5/PL-EINT7)
LCD_UD: J4.34(U/D) R28.2 R35.1
LED0_AD0: J18.13(YELLOW-) R84.2 U10.32(LED0/CFG_EXT)
LED1_AD1: R82.2 R83.2 U10.33(LED1/CFG_LDO0)
LED+: C42.1 C43.1 D32.2(CATHODE) J4.39(LED+) J4.40(LED+) U7.5(OVP)
LED-: J4.31(LED-) J4.32(LED-) R44.1 R45.1 R46.1 R47.1 U7.3(FB)
LRADC0: D43.2(CATHODE) J9.1 U1.183(LRADC0)
LVDS0-CKN: D21.1(IN1) D21.10(OUT1) J3.34 J4.17(RXCLKN-) U1.58(PD7/LCD0-D11/LVDS0-CKN/DSI0-D2N/EINK-D7/PWM0-7/PD-EINT7)
LVDS0-CKP: D21.2(IN2) D21.9(OUT2) J3.33 J4.18(RXCLKN+) U1.57(PD6/LCD0-D10/LVDS0-CKP/DSI0-D2P/EINK-D6/PWM0-6/PD-EINT6)
LVDS0-D0N: D13.2(IN2) D13.9(OUT2) J3.10 J4.8(RXIN0-) U1.52(PD1/LCD0-D3/LVDS0-D0N/DSI0-D0N/EINK-D1/PWM0-1/PD-EINT1)
LVDS0-D0P: D13.1(IN1) D13.10(OUT1) J3.9 J4.9(RXIN0+) U1.51(PD0/LCD0-D2/LVDS0-D0P/DSI0-D0P/EINK-D0/PWM0-0/PD-EINT0)
LVDS0-D1N: D13.5(IN4) D13.6(OUT4) J3.12 J4.11(RXIN1-) U1.54(PD3/LCD0-D5/LVDS0-D1N/DSI0-D1N/EINK-D3/PWM0-3/PD-EINT3)
LVDS0-D1P: D13.4(IN3) D13.7(OUT3) J3.11 J4.12(RXIN1+) U1.53(PD2/LCD0-D4/LVDS0-D1P/DSI0-D1P/EINK-D2/PWM0-2/PD-EINT2)
LVDS0-D2N: D81.1(ANODE) J3.14 J4.14(RXIN2-) U1.56(PD5/LCD0-D7/LVDS0-D2N/DSI0-CKN/EINK-D5/PWM0-5/PD-EINT5)
LVDS0-D2P: D80.1(ANODE) J3.13 J4.15(RXIN2+) U1.55(PD4/LCD0-D6/LVDS0-D2P/DSI0-CKP/EINK-D4/PWM0-4/PD-EINT4)
LVDS0-D3N: D21.4(IN3) D21.7(OUT3) J3.36 J4.20(RXIN3-) U1.60(PD9/LCD0-D13/LVDS0-D3N/DSI0-D3N/EINK-D9/PWM0-9/PD-EINT9)
LVDS0-D3P: D21.5(IN4) D21.6(OUT4) J3.35 J4.21(RXIN3+) U1.59(PD8/LCD0-D12/LVDS0-D3P/DSI0-D3P/EINK-D8/PWM0-8/PD-EINT8)
LVDS1-CKN: D19.2(IN2) D19.9(OUT2) J3.26 U1.68(PD17/LCD0-D23/LVDS1-CKN/DSI1-D2N/EINK-LEH/TWI2-SDA/UART3-RX/PD-EINT17)
LVDS1-CKP: D19.1(IN1) D19.10(OUT1) J3.25 U1.67(PD16/LCD0-D22/LVDS1-CKP/DSI1-D2P/EINK-OEH/TWI2-SCK/UART3-TX/PD-EINT16)
LVDS1-D0N: D83.1(ANODE) J3.18 U1.62(PD11/LCD0-D15/LVDS1-D0N/DSI1-D0N/EINK-D11/SPI1-CLK<DBI-SCLK>/PWM1-1/PD-EINT11)
LVDS1-D0P: D82.1(ANODE) J3.17 U1.61(PD10/LCD0-D14/LVDS1-D0P/DSI1-D0P/EINK-D10/SPI1-CS0<DBI-CSX>/PWM1-0/PD-EINT10)
LVDS1-D1N: D16.2(IN2) D16.9(OUT2) J3.20 U1.64(PD13/LCD0-D19/LVDS1-D1N/DSI1-D1N/EINK-D13/SPI1-MISO<DBI-SDI/DBI-TE/DBI-DCX>/PWM1-3/PD-EINT13)
LVDS1-D1P: D16.1(IN1) D16.10(OUT1) J3.19 U1.63(PD12/LCD0-D18/LVDS1-D1P/DSI1-D1P/EINK-D12/SPI1-MOSI<DBI-SDO>/PWM1-2/PD-EINT12)
LVDS1-D2N: D16.5(IN4) D16.6(OUT4) J3.22 U1.66(PD15/LCD0-D21/LVDS1-D2N/DSI1-CKN/EINK-D15/SPI1-CS1/UART3-CTS/PD-EINT15)
LVDS1-D2P: D16.4(IN3) D16.7(OUT3) J3.21 U1.65(PD14/LCD0-D20/LVDS1-D2P/DSI1-CKP/EINK-D14/SPI1-HOLD<DBI-DCX/DBI-WRX>/UART3-RTS/PD-EINT14)
LVDS1-D3N: D19.5(IN4) D19.6(OUT4) J3.28 U1.70(PD19/LCD0-DE/LVDS1-D3N/DSI1-D3N/EINK-STH/PWM1-5/UART4-CTS/PD-EINT19)
LVDS1-D3P: D19.4(IN3) D19.7(OUT3) J3.27 U1.69(PD18/LCD0-CLK/LVDS1-D3P/DSI1-D3P/EINK-CKH/SPI1-WP<DBI-TE>/UART4-RTS/PD-EINT18)
MCSI0-MCLK: CON1.26(MCLK_F) D7.1(IN1) D7.10(OUT1) U1.26(PE0/MCSI0-MCLK/CSI0-XHS/SPI3-CS0/LPC-LAD0/NCSI0-HSYNC/UART6-TX/PE-EINT0)
MCSI2-MCLK: CON1.28(MCLK_B) D7.2(IN2) D7.9(OUT2) U1.27(PE9/MCSI2-MCLK/TCON-FSYNC0/I2S3-MCLK/LPC-LRESET/NCSI0-D5/UART6-RI/PE-EINT9)
MCSI-RST-F: CON1.31(RESET_F) D7.5(IN4) D7.6(OUT4) U1.29(PE7/CLK-FANOUT2/HDMI-SCL/I2S3-BCLK/LPC-LAD1/NCSI0-D3/TWI11-SCK/PE-EINT7)
MCSI-RST-R: CON1.32(RESET_B) D8.4(IN3) D8.7(OUT3) U1.31(PE10/TWI4-SCK/TCON-FSYNC1/I2S3-DIN3/I2S3-DOUT3/LPC-LAD3/NCSI0-D6/UART1-RTS/PE-EINT10)
MCSI-SCK-TWI2: CON1.34(SCL) D8.2(IN2) D8.9(OUT2) R15.2 U1.32(PE1/TWI2-SCK/CSI1-XHS/SPI3-CLK/LPC-LPME/NCSI0-VSYNC/UART6-RX/PE-EINT1)
MCSI-SDA-TWI2: CON1.35(SDA) D8.1(IN1) D8.10(OUT1) R16.2 U1.33(PE2/TWI2-SDA/CSI0-XVS-FSYNC/SPI3-MOSI/LPC-LPCPD/NCSI0-PCLK/UART6-RTS/PE-EINT2)
MCSI-STBY-F: CON1.30(PWDN_F) D7.4(IN3) D7.7(OUT3) U1.28(PE6/CLK-FANOUT1/HDMI-CEC/I2S3-DIN0/I2S3-DOUT1/LPC-SERIRQ/NCSI0-D2/UART6-DTR/PE-EINT6)
MCSI-STBY-R: CON1.33(PWDN_B) D8.5(IN4) D8.6(OUT4) U1.30(PE8/CLK-FANOUT3/HDMI-SDA/I2S3-LRCK/LPC-LAD2/NCSI0-D4/TWI11-SDA/PE-EINT8)
MCSIA-CKN: CON1.14(MCN_B) D5.1(IN1) D5.10(OUT1) U1.18(PK4/MCSIA-CKN/PCIE-WAKEN/I2S4-DOUT0/I2S4-DIN1/SPI3-CS0/NCSI1-D15/JTAG-MAS-MS/PK-EINT4)
MCSIA-CKP: CON1.15(MCP_B) D5.2(IN2) D5.9(OUT2) U1.19(PK5/MCSIA-CKP/PCIE-CLKREQN/PWM1-8/PWM1-9/SPI3-CLK/NCSI1-D14/JTAG-MAS-CK/PK-EINT5)
MCSIA-D0N: CON1.11(MDN0_B) D3.4(IN3) D3.7(OUT3) U1.16(PK0/MCSIA-D0N/UART6-DCD/I2S4-BCLK/HDMI-CEC/TWI1-SDA/NCSI1-HSYNC/SGPIO-SLOAD/PK-EINT0)
MCSIA-D0P: CON1.12(MDP0_B) D3.5(IN4) D3.6(OUT4) U1.17(PK1/MCSIA-D0P/UART6-DSR/I2S4-MCLK/HDMI-SCL/TWI1-SCK/NCSI1-VSYNC/SGPIO-SCLK/PK-EINT1)
MCSIA-D1N: CON1.8(MDN1_B) D3.1(IN1) D3.10(OUT1) U1.14(PK2/MCSIA-D1N/UART6-DTR/I2S4-LRCK/HDMI-SDA/TWI5-SDA/NCSI1-PCLK/SGPIO-SDATAIN/PK-EINT2)
MCSIA-D1P: CON1.9(MDP1_B) D3.2(IN2) D3.9(OUT2) U1.15(PK3/MCSIA-D1P/UART6-RI/I2S4-DIN0/I2S4-DOUT1/TWI5-SCK/NCSI1-MCLK/SGPIO-SDATAOUT/PK-EINT3)
MCSIA-D2N: CON1.5(MDN2_B) D4.4(IN3) D4.7(OUT3) U1.12(PK6/MCSIA-D2N/TWI2-SCK/UART4-TX/UART2-RTS/SPI3-MOSI/NCSI1-D13/JTAG-MAS-DO/PK-EINT6)
MCSIA-D2P: CON1.6(MDP2_B) D4.5(IN4) D4.6(OUT4) U1.13(PK7/MCSIA-D2P/TWI2-SDA/UART4-RX/UART2-CTS/SPI3-MISO/NCSI1-D12/JTAG-MAS-DI/PK-EINT7)
MCSIA-D3N: CON1.2(MDN3_B) D4.1(IN1) D4.10(OUT1) U1.10(PK8/MCSIA-D3N/MCSI0-MCLK/UART4-RTS/UART2-TX/SPI3-CS1/NCSI1-D11/JTAG-MAS-NTRST/PK-EINT8)
MCSIA-D3P: CON1.3(MDP3_B) D4.2(IN2) D4.9(OUT2) U1.11(PK9/MCSIA-D3P/MCSI2-MCLK/UART4-CTS/UART2-RX/NCSI1-D10/JTAG-MAS-SRST/PK-EINT9)
MCSIC-CKN: CON1.23(MCN_F) D6.4(IN3) D6.7(OUT3) U1.24(PK24/MCSIC-CKN/MCSI0-MCLK/PWM0-6/TWI12-SCK/TWI10-SDA/PK-EINT24)
MCSIC-CKP: CON1.24(MCP_F) D6.5(IN4) D6.6(OUT4) U1.25(PK25/MCSIC-CKP/MCSI1-MCLK/PWM0-7/TWI12-SDA/TWI10-SCK/PK-EINT25)
MCSIC-D0N: CON1.20(MDN0_F) D6.1(IN1) D6.10(OUT1) U1.22(PK20/MCSIC-D0N/TWI2-SCK/UART3-TX/PWM0-1/NCSI1-PCLK/UART1-RTS/PK-EINT20)
MCSIC-D0P: CON1.21(MDP0_F) D6.2(IN2) D6.9(OUT2) U1.23(PK21/MCSIC-D0P/TWI2-SDA/UART3-RX/PWM0-2/NCSI1-MCLK/UART1-CTS/PK-EINT21)
MCSIC-D1N: CON1.17(MDN1_F) D5.4(IN3) D5.7(OUT3) U1.20(PK22/MCSIC-D1N/TWI3-SCK/UART3-RTS/PWM1-6/NCSI1-HSYNC/UART1-TX/PK-EINT22)
MCSIC-D1P: CON1.18(MDP1_F) D5.5(IN4) D5.6(OUT4) U1.21(PK23/MCSIC-D1P/TWI3-SDA/UART3-CTS/PWM1-7/NCSI1-VSYNC/UART1-RX/PK-EINT23)
MDI0+: J18.2(TD0+) U10.1(MDI[0]+)
MDI0-: J18.3(TD0-) U10.2(MDI[0]-)
MDI1+: J18.4(TD1+) U10.4(MDI[1]+)
MDI1-: J18.7(TD1-) U10.5(MDI[1]-)
MDI2+: J18.5(TD2+) U10.6(MDI[2]+)
MDI2-: J18.6(TD2-) U10.7(MDI[2]-)
MDI3+: J18.8(TD3+) U10.9(MDI[3]+)
MDI3-: J18.9(TD3-) U10.10(MDI[3]-)
PA-SHDN-PE15: U1.133(PE15/SPI3-CS1/PWM1-9/IR-RX/TWI9-SDA/PE-EINT15) ; also on sheet 13
PC2: D60.2(IN2) D60.9(OUT2) J16.18 U1.149(PC2/NAND-CLE/SPI0-MOSI/SPIF0-MOSI/PC-EINT2)
PC3: D60.5(IN4) D60.6(OUT4) J16.20 U1.147(PC3/NAND-CE1/SPI0-CS0/SPIF0-CS0/PC-EINT3)
PC4: D60.4(IN3) D60.7(OUT3) J16.19 U1.148(PC4/NAND-CE0/SPI0-MISO/SPIF0-MISO/PC-EINT4)
PC12: D60.1(IN1) D60.10(OUT1) J16.17 U1.150(PC12/NAND-DQS/SPI0-CLK/SPIF0-CLK/PC-EINT12)
PCIE1-REFCLKN: U1.128(COMB1-REF-CLKN) ; also on sheet 11
PCIE1-REFCLKP: U1.127(COMB1-REF-CLKP) ; also on sheet 11
PCIE1-RXN: U1.126(PCIE1-RX0N/USB2-U3-RX0N) ; also on sheet 11
PCIE1-RXP: U1.125(PCIE1-RX0P/USB2-U3-RX0P) ; also on sheet 11
PCIE1-TXN: U1.122(PCIE1-TX0N/USB2-U3-TX0N) ; also on sheet 11
PCIE1-TXP: U1.121(PCIE1-TX0P/USB2-U3-TX0P) ; also on sheet 11
PCIE-3V3: C11.1 C12.1 C13.1 C26.2 C27.1 C88.1 C95.1 C96.1 C97.1 C98.1 CON2.12(VCCS) CON2.13(VCCS) L2.2 R9.1 R19.2 R119.2 ; also on sheet 11
PCIE-CLKREQN: U1.131(PE14/SPI3-MOSI/PWM1-8/PCIE-CLKREQN/IR-RX/TWI9-SCK/PE-EINT14) ; also on sheet 11
PCIE-PERSTN: U1.130(PE13/SPI3-CLK/PCIE-PERSTN/UART1-RX/PE-EINT13) ; also on sheet 11
PCIE-WAKEN: U1.132(PE12/SPI3-CS0/I2S3-DOUT0/I2S3-DIN1/PCIE-WAKEN/UART1-TX/PE-EINT12) ; also on sheet 11
PHYRSTB: CE7.2 RE2.2 U1.99(PH16/UART5-CTS/IR-TX/PH-EINT16) U10.12(PHYRSTB)
PK10: D57.5(IN4) D57.6(OUT4) J16.8 U1.186(PK10/MCSIB-D0N/UART6-TX/PWM0-3/NCSI1-D9/PK-EINT10)
PK11: D57.4(IN3) D57.7(OUT3) J16.7 U1.187(PK11/MCSIB-D0P/UART6-RX/PWM0-4/NCSI1-D8/PK-EINT11)
PK12: D58.2(IN2) D58.9(OUT2) J16.10 U1.184(PK12/MCSIB-D1N/UART6-RTS/PWM0-5/NCSI1-D7/PK-EINT12)
PK13: D58.1(IN1) D58.10(OUT1) J16.9 U1.185(PK13/MCSIB-D1P/UART6-CTS/PWM0-6/NCSI1-D6/PK-EINT13)
PK16: D57.2(IN2) D57.9(OUT2) J16.6 U1.3(PK16/MCSIB-D2N/TWI3-SCK/UART2-TX/PWM0-9/NCSI1-D3/PK-EINT16)
PK17: D57.1(IN1) D57.10(OUT1) J16.5 U1.4(PK17/MCSIB-D2P/TWI3-SDA/UART2-RX/PWM1-0/NCSI1-D2/PK-EINT17)
PL12: D59.5(IN4) D59.6(OUT4) J16.16 U1.171(PL12/S-UART1-TX/S-TWI1-SCK/S-TWI2-SCK/S-IR-RX/PL-EINT12)
PL13: D59.4(IN3) D59.7(OUT3) J16.15 U1.170(PL13/S-UART1-RX/S-TWI1-SDA/S-TWI2-SDA/PL-EINT13)
PM5-BEEP: R81.1 U1.169(PM5/S-UART0-RX/S-TWI2-SDA/S-TWI1-SDA/S-UART1-RX/S-PWM0-1/S-IR-RX/PM-EINT5)
PWRON: C46.1 D41.2(CATHODE) K2.2 U1.168(PWRON)
REGOUT: L6.1 U10.30(REG_OUT)
RGMII0-CLK-25M: R86.1 U1.82(PH15/UART5-RTS/LEDC/DSI-TRIG-LCD-TE1/RGMII0-EPHY-25/50M/PH-EINT15)
RGMII0-CLKIN-125M: RE12.1 U1.83(PH3/TWI1-SDA/I2S2-BCLK/RGMII0-CLKIN/RMII0-RXER/SPI1-MISO/PH-EINT3)
RGMII0-MDC: U1.98(PH8/DMIC-CLK/SPI2-CLK/RGMII0-MDC/PH-EINT8) U10.13(MDC)
RGMII0-MDIO: RE3.2 U1.97(PH9/DMIC-DATA0/SPI2-CS0/RGMII0-MDIO/PH-EINT9) U10.14(MDIO)
RGMII0-RXCK: RE10.1 U1.84(PH12/DMIC-DATA3/SPI2-CS1/RGMII0-RXCK/RMII0-NULL/PH-EINT12)
RGMII0-RXCTL: RE11.1 U1.85(PH2/TWI1-SCK/I2S2-MCLK/RGMII0-RXCTL/RMII0-CRS-DV/SPI1-CS1/PH-EINT2)
RGMII0-RXD0: RE9.1 U1.86(PH1/TWI0-SDA/I2S2-DOUT3/I2S2-DIN3/RGMII0-RXD0/RMII0-RXD0/TWI3-SDA/SPI1-WP/PH-EINT1) U10.25(RXD0/RXDLY)
RGMII0-RXD1: RE8.1 U1.87(PH0/TWI0-SCK/I2S2-DOUT2/I2S2-DIN2/RGMII0-RXD1/RMII0-RXD1/TWI3-SCK/SPI1-HOLD/PH-EINT0) U10.24(RXD1/TXDLY)
RGMII0-RXD2: RE5.1 U1.88(PH11/DMIC-DATA2/SPI2-MISO/RGMII0-RXD2/RMII0-NULL/PH-EINT11) U10.23(RXD2/PLLOFF)
RGMII0-RXD3: RE13.1 U1.89(PH10/DMIC-DATA1/SPI2-MOSI/RGMII0-RXD3/RMII0-NULL/PH-EINT10) U10.22(RXD3/PHYAD0)
RGMII0-TXCK: RE7.1 U1.90(PH6/UART3-RTS/I2S2-DOUT1/I2S2-DIN0/RGMII0-TXCK/RMII0-TXCK/SPI1-CLK/PH-EINT6)
RGMII0-TXCTL: RE6.1 U1.91(PH7/UART3-CTS/SPI2-CS2/DSI-TRIG-LCD-TE1/RGMII0-TXCTL/RMII0-TXEN/PH-EINT7)
RGMII0-TXD0: U1.92(PH5/UART3-RX/I2S2-DIN1/I2S2-DOUT0/RGMII0-TXD0/RMII0-TXD0/SPI1-MOSI/PH-EINT5) U10.18(TXD0)
RGMII0-TXD1: U1.93(PH4/UART3-TX/SPI2-CS3/I2S2-LRCK/RGMII0-TXD1/RMII0-TXD1/SPI1-CS0/PH-EINT4) U10.17(TXD1)
RGMII0-TXD2: U1.94(PH14/UART5-RX/RGMII0-TXD2/RMII0-NULL/TWI7-SCK/PH-EINT14) U10.16(TXD2)
RGMII0-TXD3: U1.96(PH13/UART5-TX/RGMII0-TXD3/RMII0-NULL/TWI7-SDA/PH-EINT13) U10.15(TXD3)
RSET: RE4.2 U10.39(RSET)
RTC-IN: D37.2(CATHODE) J8.2 U1.166(BKUPBAT)
RXC/PHYAD1: RE10.2 RE14.2 U10.27(RXC/PHYAD1)
RXCTL/PHYAD2: RE11.2 RE15.2 U10.26(RXCTL/PHYAD2)
S-TWI0-CTP0-SCK: D20.2(IN2) D20.9(OUT2) J3.2 J5.6 R25.1 U1.178(PL8/S-TWI1-SCK/S-UART1-TX/S-TWI0-SCK/S-TWI2-SCK/S-PWM0-6/PL-EINT8)
S-TWI0-CTP0-SDA: D20.1(IN1) D20.10(OUT1) J3.1 J5.5 R24.1 U1.179(PL9/S-TWI1-SDA/S-UART1-RX/S-TWI0-SDA/S-TWI2-SDA/S-PWM0-7/PL-EINT9)
SDC0-CLK: D38.1(IN1) D38.10(OUT1) J7.5(CLK) U1.74(PF2/SDC0-CLK/UART0-TX/TRACE-CLK/PF-EINT2)
SDC0-CMD: D35.2(CATHODE) J7.3(CMD) R52.2 U1.75(PF1/SDC0-CMD/JTAG-DO/TRACE-DATA2/PF-EINT1)
SDC0-D0: D38.2(IN2) D38.9(OUT2) J7.7(DAT0) U1.73(PF3/SDC0-D0/JTAG-DI/TRACE-DATA0/UART5-CTS/TWI2-SDA/PF-EINT3)
SDC0-D1: D38.4(IN3) D38.7(OUT3) J7.8(DAT1) U1.72(PF0/SDC0-D1/JTAG-MS/TRACE-DATA3/UART5-RTS/TWI2-SCK/PF-EINT0)
SDC0-D2: D33.2(CATHODE) J7.1(DAT2) U1.77(PF5/SDC0-D2/JTAG-CK/TRACE-DATA1/UART5-TX/PF-EINT5)
SDC0-D3: D34.2(CATHODE) J7.2(DAT3) U1.76(PF4/SDC0-D3/UART0-RX/UART5-RX/PF-EINT4)
SDC0-DET: D38.5(IN4) D38.6(OUT4) R53.1 U1.71(PF6/PF-EINT6)
TRM-CTR: C62.2 J18.1(GND)
TWI8-SCK: U1.115(PB9/UART0-TX/I2S0-DIN2/I2S0-DOUT2/PWM1-1/WATCHDOG-SIG/LCD0-D16/TWI8-SCK/TWI0-SCK/PB-EINT9) ; also on sheet 13
TWI8-SDA: U1.116(PB10/UART0-RX/I2S0-DIN3/I2S0-DOUT3/PWM1-2/PLL-LOCK-DBG/LCD0-D17/TWI8-SDA/TWI0-SDA/PB-EINT10) ; also on sheet 13
TXC: RE7.2 U10.20(TXC)
TXCTL: RE6.2 U10.19(TXCTL)
UART0-RX: U1.107(PB1/UART2-RX/UART0-RX/SPI2-CLK/LCD0-D1/JTAG-CK/PB-EINT1) ; also on sheet 12
UART0-TX: U1.106(PB0/UART2-TX/UART0-TX/SPI2-CS0/DSI-TRIG-LCD-TE1/LCD0-D0/JTAG-MS/PB-EINT0) ; also on sheet 12
UART2-RX: D51.1(ANODE) R69.1 U1.105(PJ27/PWM1-9/UART4-CTS/UART2-RX/DSI-TRIG-LCD-TE1/TWI5-SDA/SPI3-CS0/LCD0-D17/PJ-EINT27)
UART2-TX: R74.2 U1.104(PJ26/PWM1-8/UART4-RTS/UART2-TX/TWI5-SCK/SPI3-MISO/LCD0-D16/PJ-EINT26) U9.4(DI)
UART3-RX: D55.2(IN2) D55.9(OUT2) J14.3 R77.2 U1.101(PJ23/PWM1-5/UART3-RX/UART2-CTS/TWI7-SDA/TWI3-SDA/TWI11-SDA/LCD0-D9/PJ-EINT23)
UART3-TX: D55.1(IN1) D55.10(OUT1) J14.2 R78.2 U1.100(PJ22/PWM1-4/UART3-TX/UART2-RTS/TWI7-SCK/TWI3-SCK/TWI11-SCK/LCD0-D8/PJ-EINT22)
UART4-RX: D55.4(IN3) D55.7(OUT3) J15.3 R79.2 U1.103(PJ25/PWM1-7/UART4-RX/TWI4-SDA/SPI3-MOSI/PJ-EINT25)
UART4-TX: D55.5(IN4) D55.6(OUT4) J15.2 R80.2 U1.102(PJ24/PWM1-6/UART4-TX/TWI4-SCK/SPI3-CLK/PJ-EINT24)
USB0-DM: U1.117(USB0-DM) ; also on sheet 12
USB0-DP: U1.118(USB0-DP) ; also on sheet 12
USB1-DM: U1.119(USB1-DM) ; also on sheet 12
USB1-DP: U1.120(USB1-DP) ; also on sheet 12
USB2-DM: U1.123(USB2-DM) ; also on sheet 11
USB2-DP: U1.124(USB2-DP) ; also on sheet 11
VCOM: J4.1(VCOM) R30.2 R36.1
VGH: C31.1 C32.1 D27.2(CATHODE) J4.38(VGH) R29.2 R32.2
VGL: C34.1 C35.1 D30.1(ANODE) J4.35(VGL) R33.2 R37.2
XTAL-25MIN: CE15.2 U10.36(XTAL_IN) X1.3
XTAL-25MOUT: CE14.2 R86.2 U10.37(XTAL_OUT/EXT_CLK) X1.1
N39839: J7.9(CD#) R51.2 R53.2
N638326: J18.14(YELLOW+) R85.1
N638520: J18.11(GREEN+) R82.1
N5679088: C1.2 L1.1 U2.6(LX)
N5679096: C1.1 U2.1(BS)
N5679154: C4.2 R4.2 R7.1 U2.3(FB/OUT)
N16925291: D32.1(ANODE) L5.2 U7.1(SW)
N17131711: D70.2 R88.1
N17175777: Q1.3(COLLECTOR) R71.2 R72.1 U9.2(~{RE}) U9.3(DE)
N17175783: D51.2(CATHODE) U9.1(RO)
N17177143: C8.2 L2.1 U3.6(LX)
N17177153: C11.2 R9.2 R11.1 U3.3(FB/OUT)
N17255318: Q2.1(BASE) R81.2
N17255336: D56.1(ANODE) J17.2 Q2.3(COLLECTOR)
N17865326: Q1.1(BASE) R74.1
N17865327: C61.2 R71.1
N17914651: C29.2 C36.1 D31.1(ANODE) L4.2 U6.1(SW)
N17914681: C29.1 D26.3
N17914691: C37.2 D29.1 R33.1
N17914697: R39.1 R42.1 U6.3(FB)
N17914762: C30.1 D26.2 R29.1
N17915278: J4.6(STBYB) R17.2 R18.1
N18037700: R233.2 U3.4(EN)
N18104730: CON2.17(HPD) R21.2
N18104732: CON2.22(LED_EN) R22.2
N18104734: CON2.23(LED_PWM) R26.2
N18105041: C21.2 CON2.3(Lane1N)
N18105043: C22.2 CON2.4(Lane1P)
N18105045: C25.2 CON2.9(AXU_CH_P)
N18105047: C28.2 CON2.10(AXU_CH_N)
N18105049: C23.2 CON2.6(Lane0N)
N18105059: C24.2 CON2.7(Lane0P)
N18148334: C89.2 L7.1 U43.6(LX)
N18148344: C92.2 R116.1 R117.2 U43.3(FB/OUT)
N18243800: R157.2 R158.1 U44.1(FB)
N18243874: C323.2 R159.2 U44.5(VCC)
N18244524: C89.1 U43.1(BS)
N18244525: C8.1 U3.1(BS)
N18245140: J2.3 R238.1 R239.2
N18245142: J2.2 U44.2(EN)
N18246656: C322.1 R156.1
N18248395: D2.1(ANODE) R6.2 R240.1
N18249325: D2.2(CATHODE) R241.2
N18250408: C36.2 D29.3

Not connected (* = marked no-connect by the designer): CON2 1(NC) 14(NC) 24(NC) 25(NC) 30(NC); FID1 1(TP)*; FID2 1(TP)*; FID3 1(TP)*; FID4 1(TP)*; H1 1(TP); H2 1(TP); H3 1(TP); H4 1(TP); J1 4 5 6* 7*; J2 1; J4 4(NC) 23(NC) 24(NC) 26(NC) 27(DIMO) 36(NC) 37(NC); J18 15(SHELL1)* 16(SHELL2)* 17(FIX1)* 18(FIX2)* 19(G+)* 20(G-)* 21(Y-)* 22(Y+)*; TP1 1(TP); TP2 1(TP); U1 1(PK14/MCSIB-CKN/PCIE-PERSTN/PWM0-7/NCSI1-D5/PK-EINT14) 2(PK15/MCSIB-CKP/PWM0-8/NCSI1-D4/PK-EINT15) 5(PK18/MCSIB-D3N/MCSI1-MCLK/UART2-RTS/PWM1-1/NCSI1-D1/TWI9-SCK/PK-EINT18) 141(TYPEC-RX2P/U3-RX0P/DP/EDP-TX2P) 142(TYPEC-RX2N/U3-RX0N/DP/EDP-TX2N) 143(TYPEC-TX2P/U3-TX0P/DP/EDP-TX3P) 144(TYPEC-TX2N/U3-TX0N/DP/EDP-TX3N) 146(PC7/NAND-RB1/SPI0-CS1/SPIF0-DQS/PC-EINT7) 151(PC15/NAND-DQ1/SDC2-D2/SDC3-D2/SPI0-WP/SPIF0-WP/PC-EINT15) 152(PC16/NAND-DQ0/SDC2-D7/SDC3-D7/SPI0-HOLD/SPIF0-HOLD/PC-EINT16) 153(PC13/NAND-DQ3/SDC2-D1/SDC3-D1/PC-EINT13) 154(PC14/NAND-DQ2/SDC2-D6/SDC3-D6/PC-EINT14) 159(PMU-IRQ) 160(PMU-SCK) 161(PMU-SDA) 176(PL6/S-JTAG-DO/S-UART0-TX/S-SPI0-MOSI/S-IR-RX/S-PWM0-4/PL-EINT6); U10 34(LED2/CFG_LDO1); U14 14(RESERVED)

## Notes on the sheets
sheet 1
- 修改日志（Change
  Logs）
- V1.3
- 首次对外发布版本（First
  release）
- 1  新增PCIE接口(Newly added PCIE interface)
- V1.6
- 2  新增EDP接口(Add a new EDP interface)
- 3 USB接口更改为2.0接口(Change the USB interface to 2.0 interface.)
- V1.7
- 1  修改电源过压保护电路(Modify the overvoltage protection circuit of the power supply.)（02）
- V1.8
- 1  PCIE电路修改（PCIE circuit modification）（07）
- 2  PCIE电路修改（PCIE circuit modification）（07）
sheet 2
- 注意：
  专用接口-PMU-IRQ/PMU-SCK/PMU-SDA，禁止使用
  Note:
  Special interface - PMU-IRQ/PMU-SCK/PMU-SDA, do not use
- 1.if not used USB3.0&PCIE2.1 COMB0/1-CLKP/N
  tie to GND,power&signal pin can floating
  2.if used USB3.0,COMB0/1-CLKP/N tie to GND,PCIE-TEST tie to test port.
  3.if used PCIE2.1,PCIE-TEST tie to test port.
- 3.3V  PB PH PJ PL PD
- 1.8V  PM PK PE PC
- 注意：
  核心板供电电流需要1.5A@5V以上。
  Note:
  The power supply current of the core board
  needs more than 1.5A@5V
- NOTE:Combo0 100nF Cap placement
  need to close SOC：
  C139/C140/C141/C142
- 注意：
  LVDS和MIPI信号定义不一样，
  MIPI屏连接DSI这类名称信号线。
  Note:
  The definitions of LVDS and
  MIPI signals are different.
   The MIPI screen is connected
  to signal lines such as DSI..
sheet 3
- DCIN
- R1
- Vset=
- (R1+R2)X1.25
- R2
- R2
- 9V<VIN<18V
- 4.5V<VIN<18V
- 4.5V<VIN<18V
sheet 4
- Camera
- 注意：
  MCSIA和 MCSIB、MCSIC 和 MCSID 才能组合成 4line 使用，MCSIA 和
  MCSIB 用作 4line 时，需使用 MCSIA
  的 CLK，MCSIB 的 CLK 可以悬空，也可以用作普通 IO，其中
  MCSIA0、MCSIA1、MCSIB0、MCSIB1
  依次对应 MCSI0/1/2/3；MCSIC 和 MCSID 用作 4line 时，需使用
  MCSIC 的 CLK，MCSID 的 CLK
  可以悬空，也可以用作普通 IO，其中
  MCSIC0、MCSIC1、MCSID0、MCSID1 依次对应 MCSI0/1/2/3
  Attention:
  MCSIA and MCSIB, MCSIC and MCSID can be combined to form 4line
  When MCSIA and MCSIB are used as 4Lines,
  use MCSIA
  The CLK of MCSIB can be suspended or used as normal
  IO, where MCSIA0, MCSIA1, MCSIB0, and MCSIB1 are displayed
  Corresponding to MCSI0/1/2/3;
  MCSIC and MCSID are used as 4lines
  ", the CLK of MCSIC and CLK of MCSID are required
  Can be suspended, can also be used as ordinary IO,where
  MCSIC0, MCSIC1, MCSID0, and MCSID1 correspond in sequence
  MCSI0/1/2/3
- 1.8V
sheet 5
- LCD
- MIPI/LVDS
- EDP
- Design for ESD test,
  Option for cost down
- Please confirm the voltage
  level matching of BL-PWMI signal.
- 9.43V
- 3.6V
- 9.43V
- LCD   select
- 此处上拉电平跟IO电平一致
  The pull-up level here is consistent with the IO level
sheet 6
- ETH
- 20mil
- 20mil
- 20mil
- PHY RESET/INTB
- Close to PHY PIN11 and PIN40 for Analog Power
- Enable/Disable PLL @ ALDPS
- Pull-up to disable PLL @ ALDPS mode.
- Close to PHY PIN29 for Digital Power & SWR
- Close to  CORE
- RGMII TXC/RXC Delay Config.
- Pull-up for additional 2ns delay to TXC/RXC for data latching.
- PHY Address Config.
- Crystal Case
sheet 7
- HDMI
- Differential pairs
  Z0= 100 ohm
- Max 500mA
- Max 1mA
- 修复HCEC与HDMI-HCEC连接
  Fix HCEC connection error with HDMI-HCEC
- 注意，此处信号为TypeA排列，
  和TypeB,C座子信号排列不同
sheet 8
- 485
- UART3
- UART4
sheet 9
- GPIO
- BEEP
sheet 10
- TF
- RTC
- 内部有上拉，可以NC R10,R11
  There is an internal pull-up, and it can be NC R10, R11.
- SDIO2.0
- 此处上拉电平跟IO电平一致
  The pull-up level here is consistent with the IO level
- 此插座可扩展按键电路
  This socket can expand the key circuit.
